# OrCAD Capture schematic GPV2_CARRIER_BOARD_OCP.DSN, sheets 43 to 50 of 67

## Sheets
43 049 I2C GPIO: size C
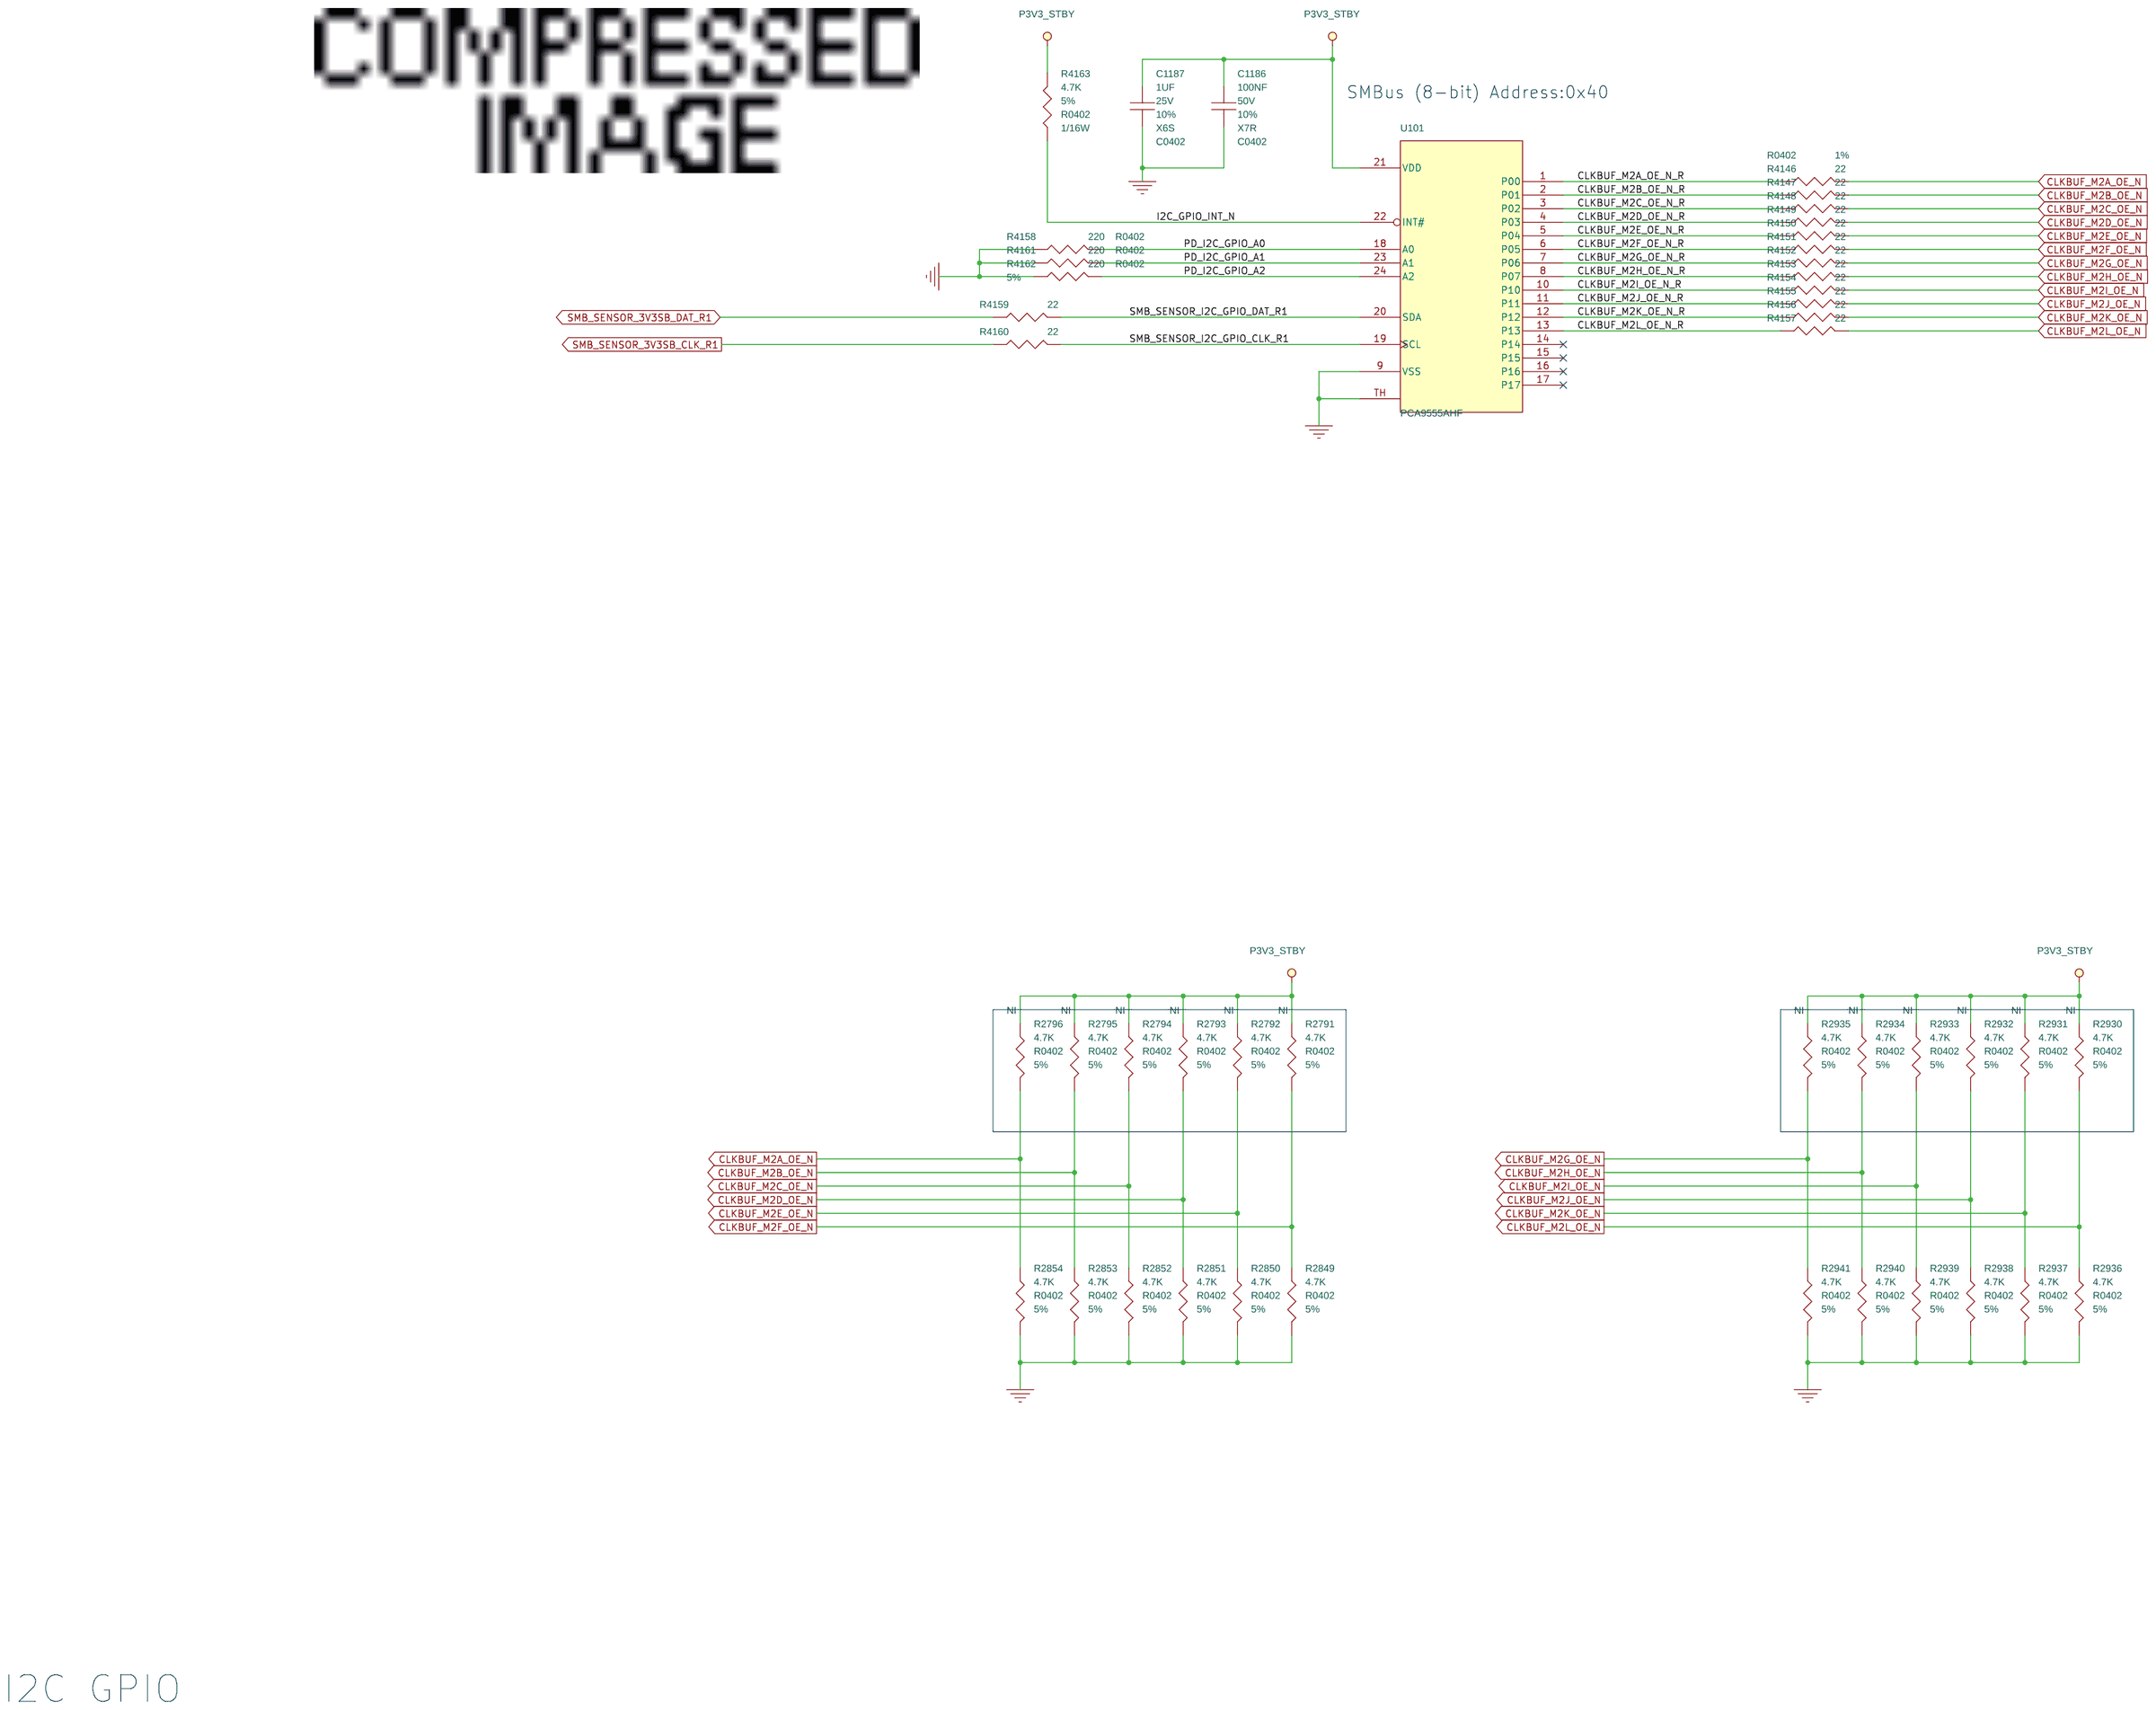
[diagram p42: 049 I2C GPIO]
44 050 Level Shifter 3: size C
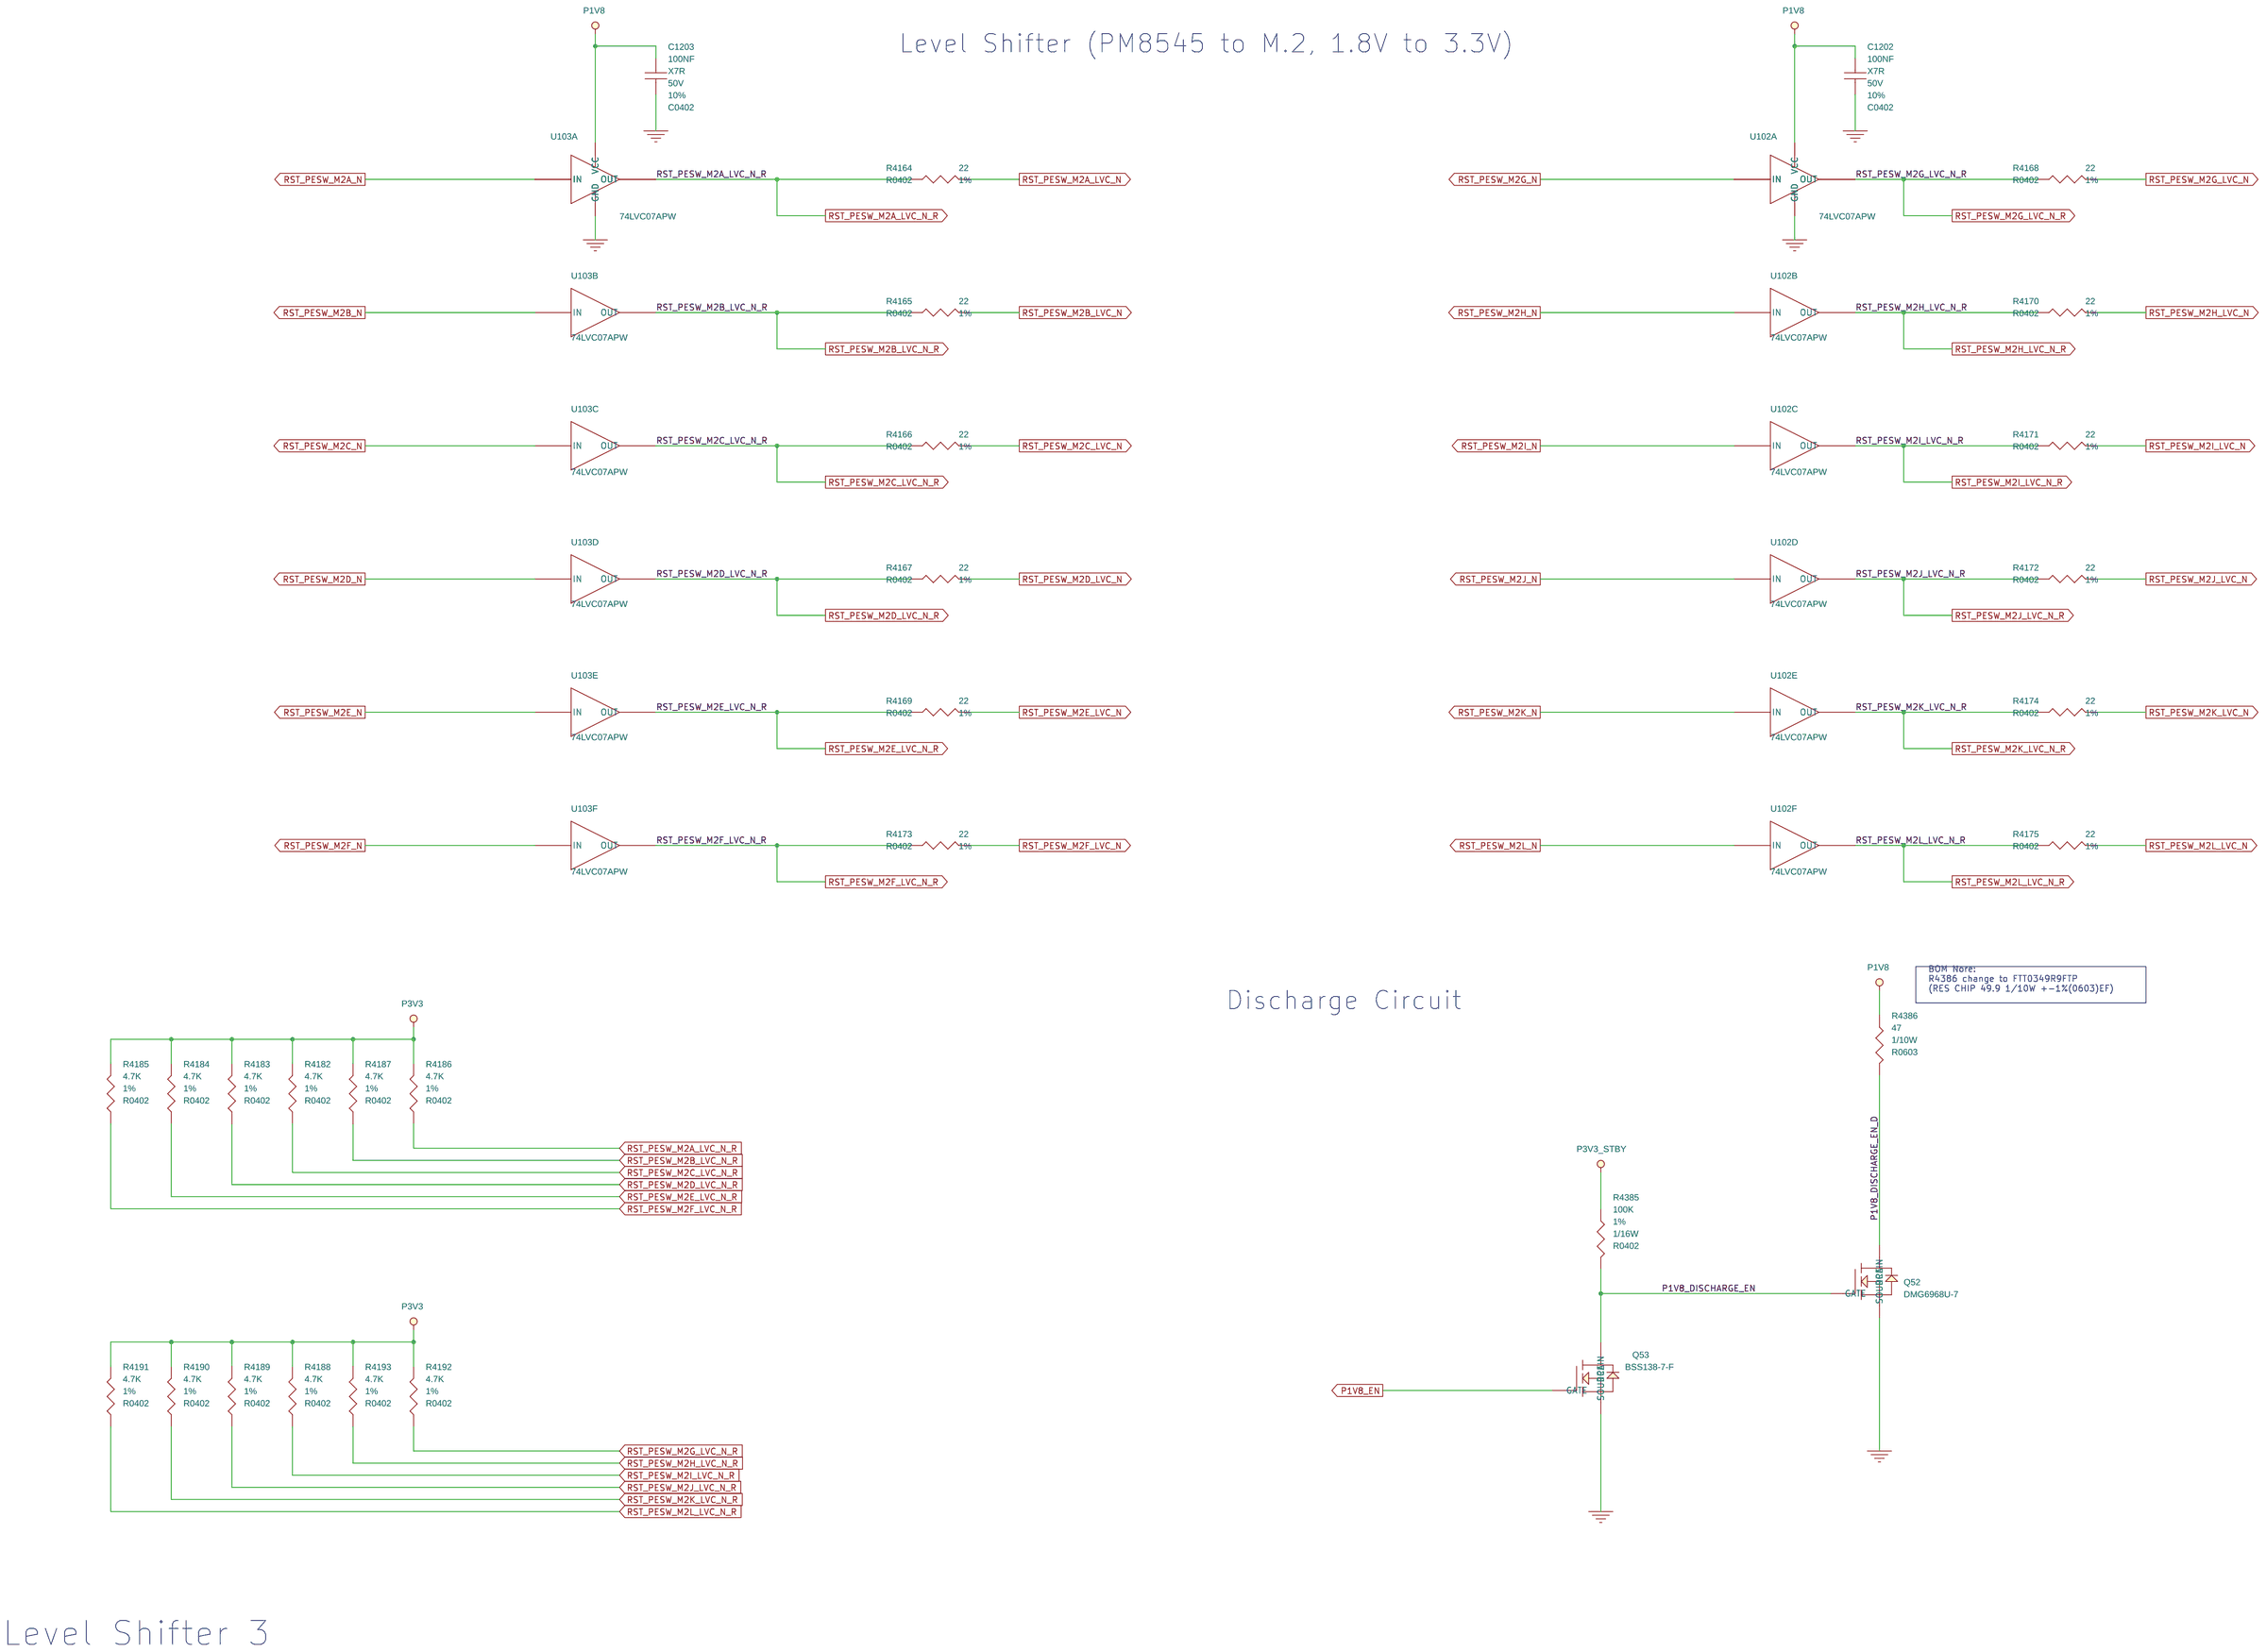
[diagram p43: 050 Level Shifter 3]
45 051 TEMP SENSOR & FRU: size C
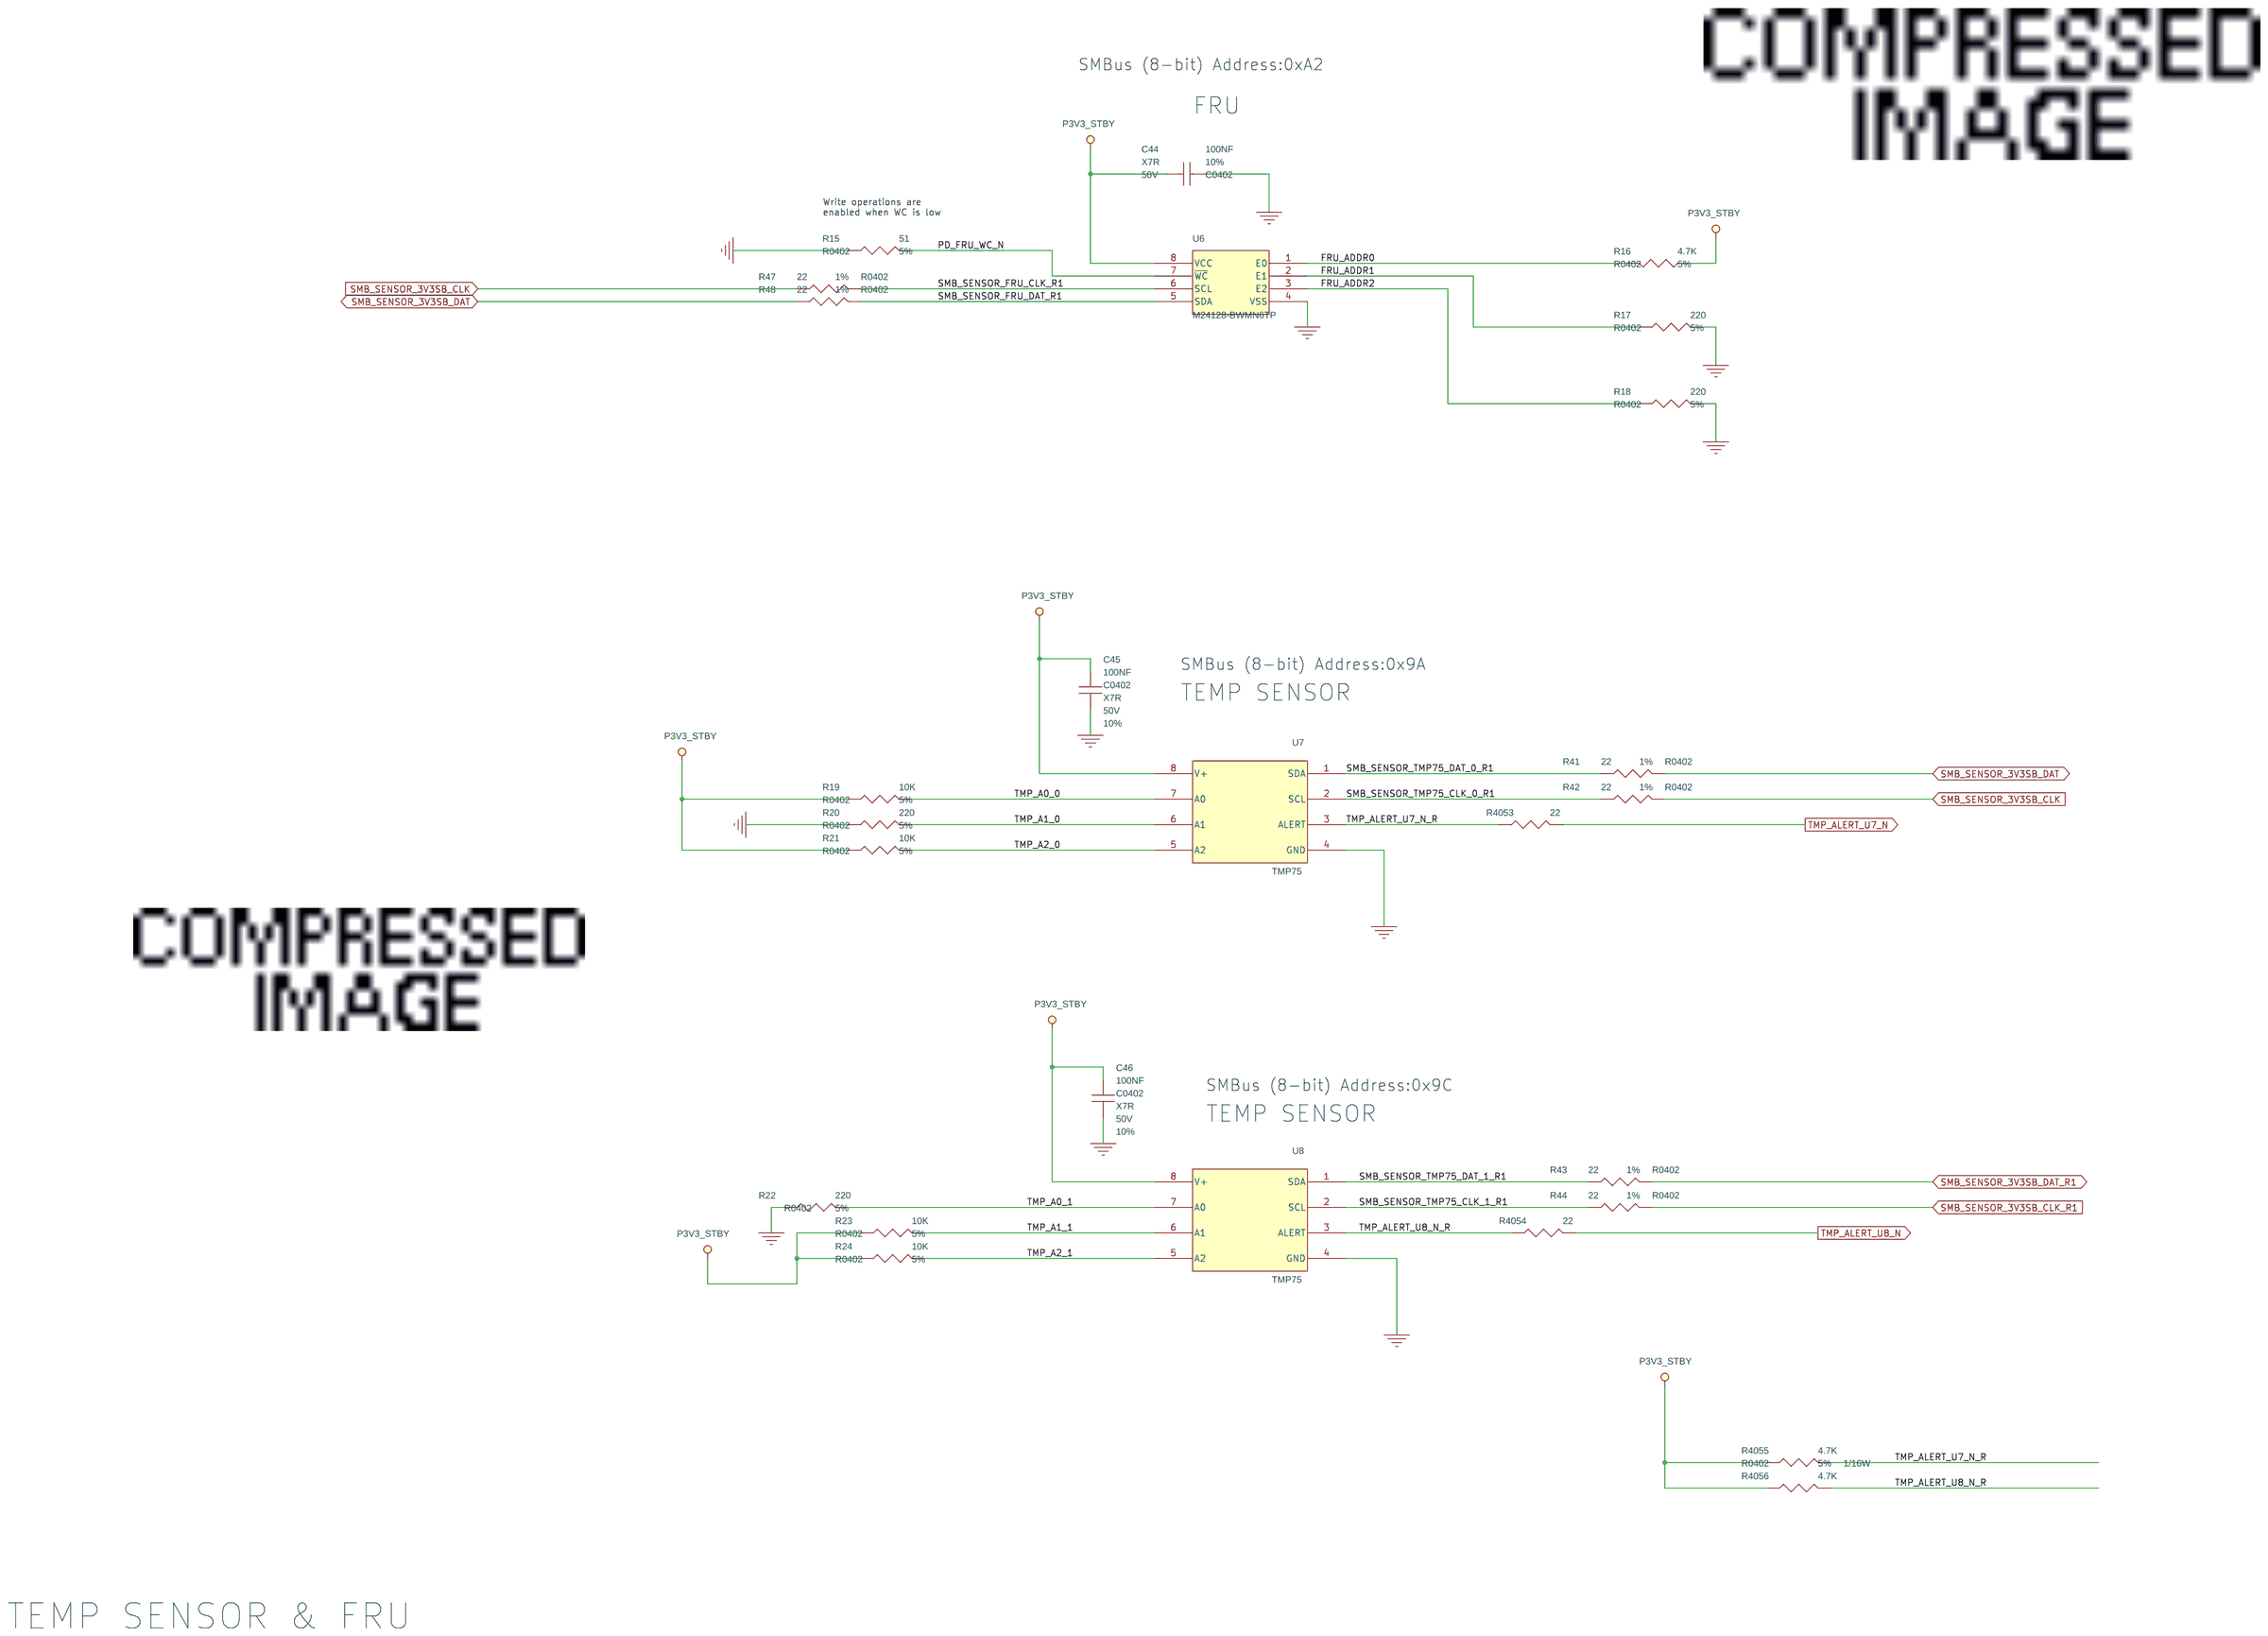
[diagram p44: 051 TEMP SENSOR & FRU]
46 052 BIC_SNOWLAKE 1: size C
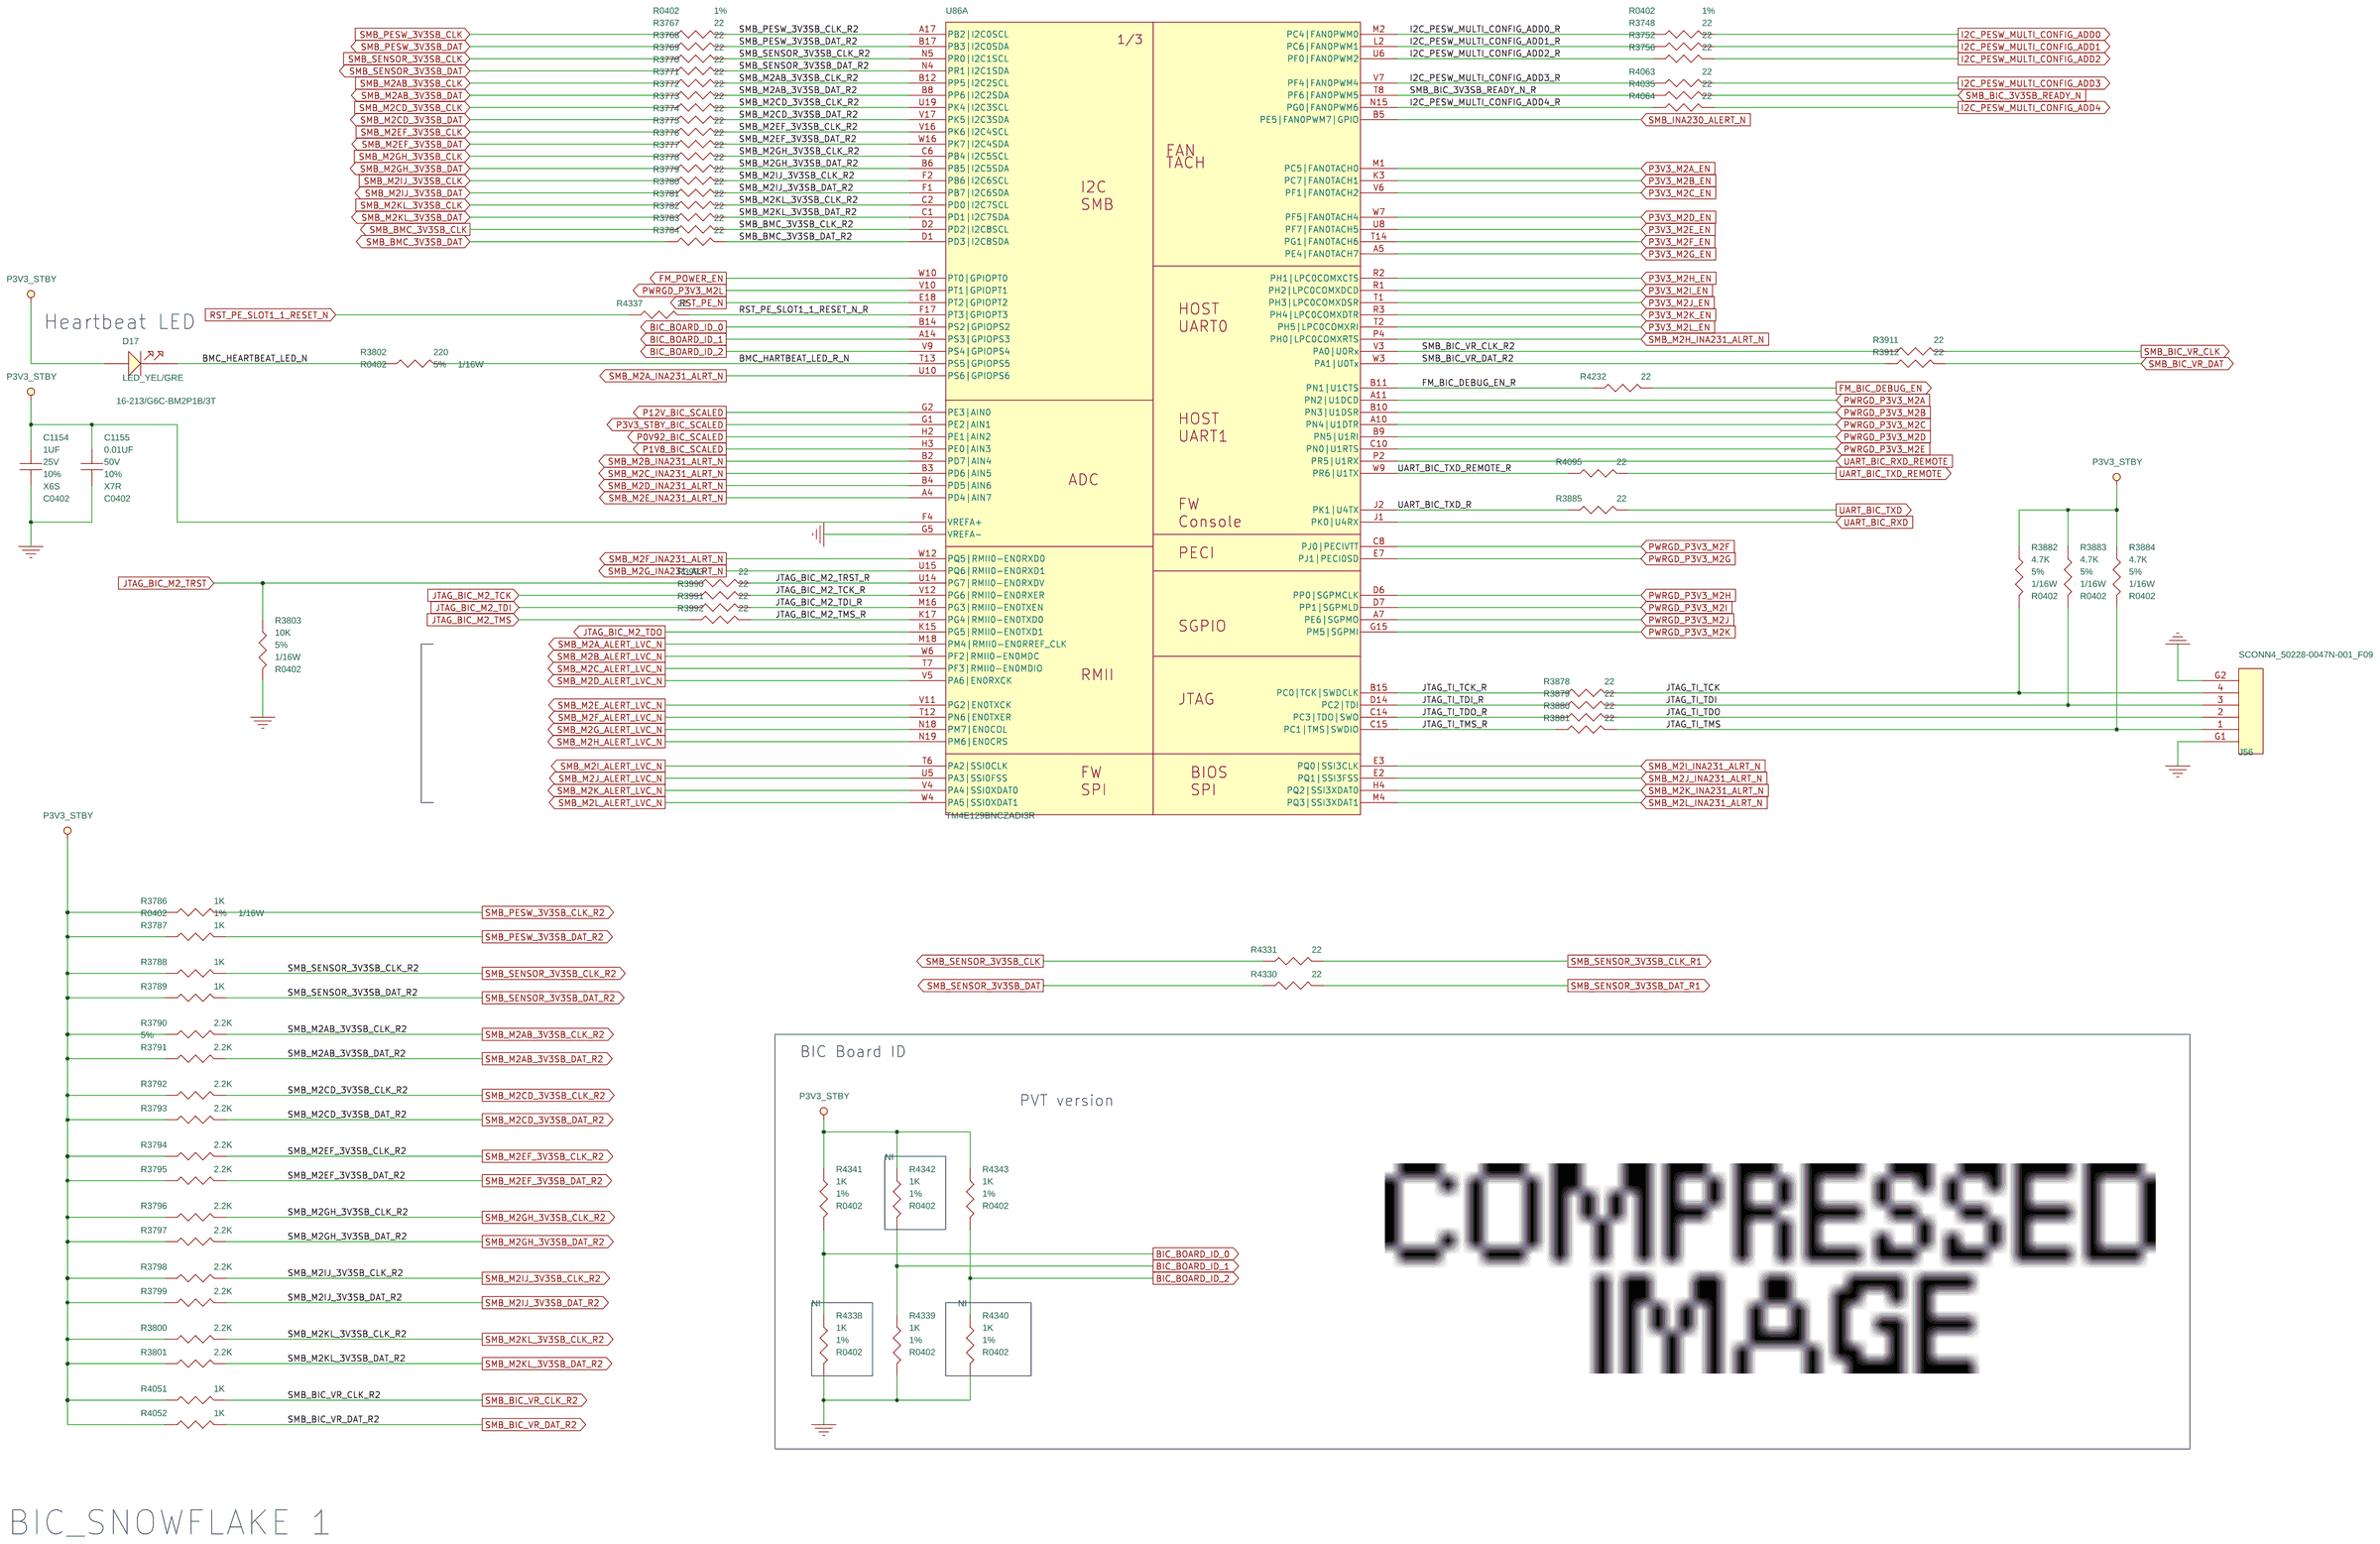
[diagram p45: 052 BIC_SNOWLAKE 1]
47 053 BIC_SNOWLAKE 2: size C
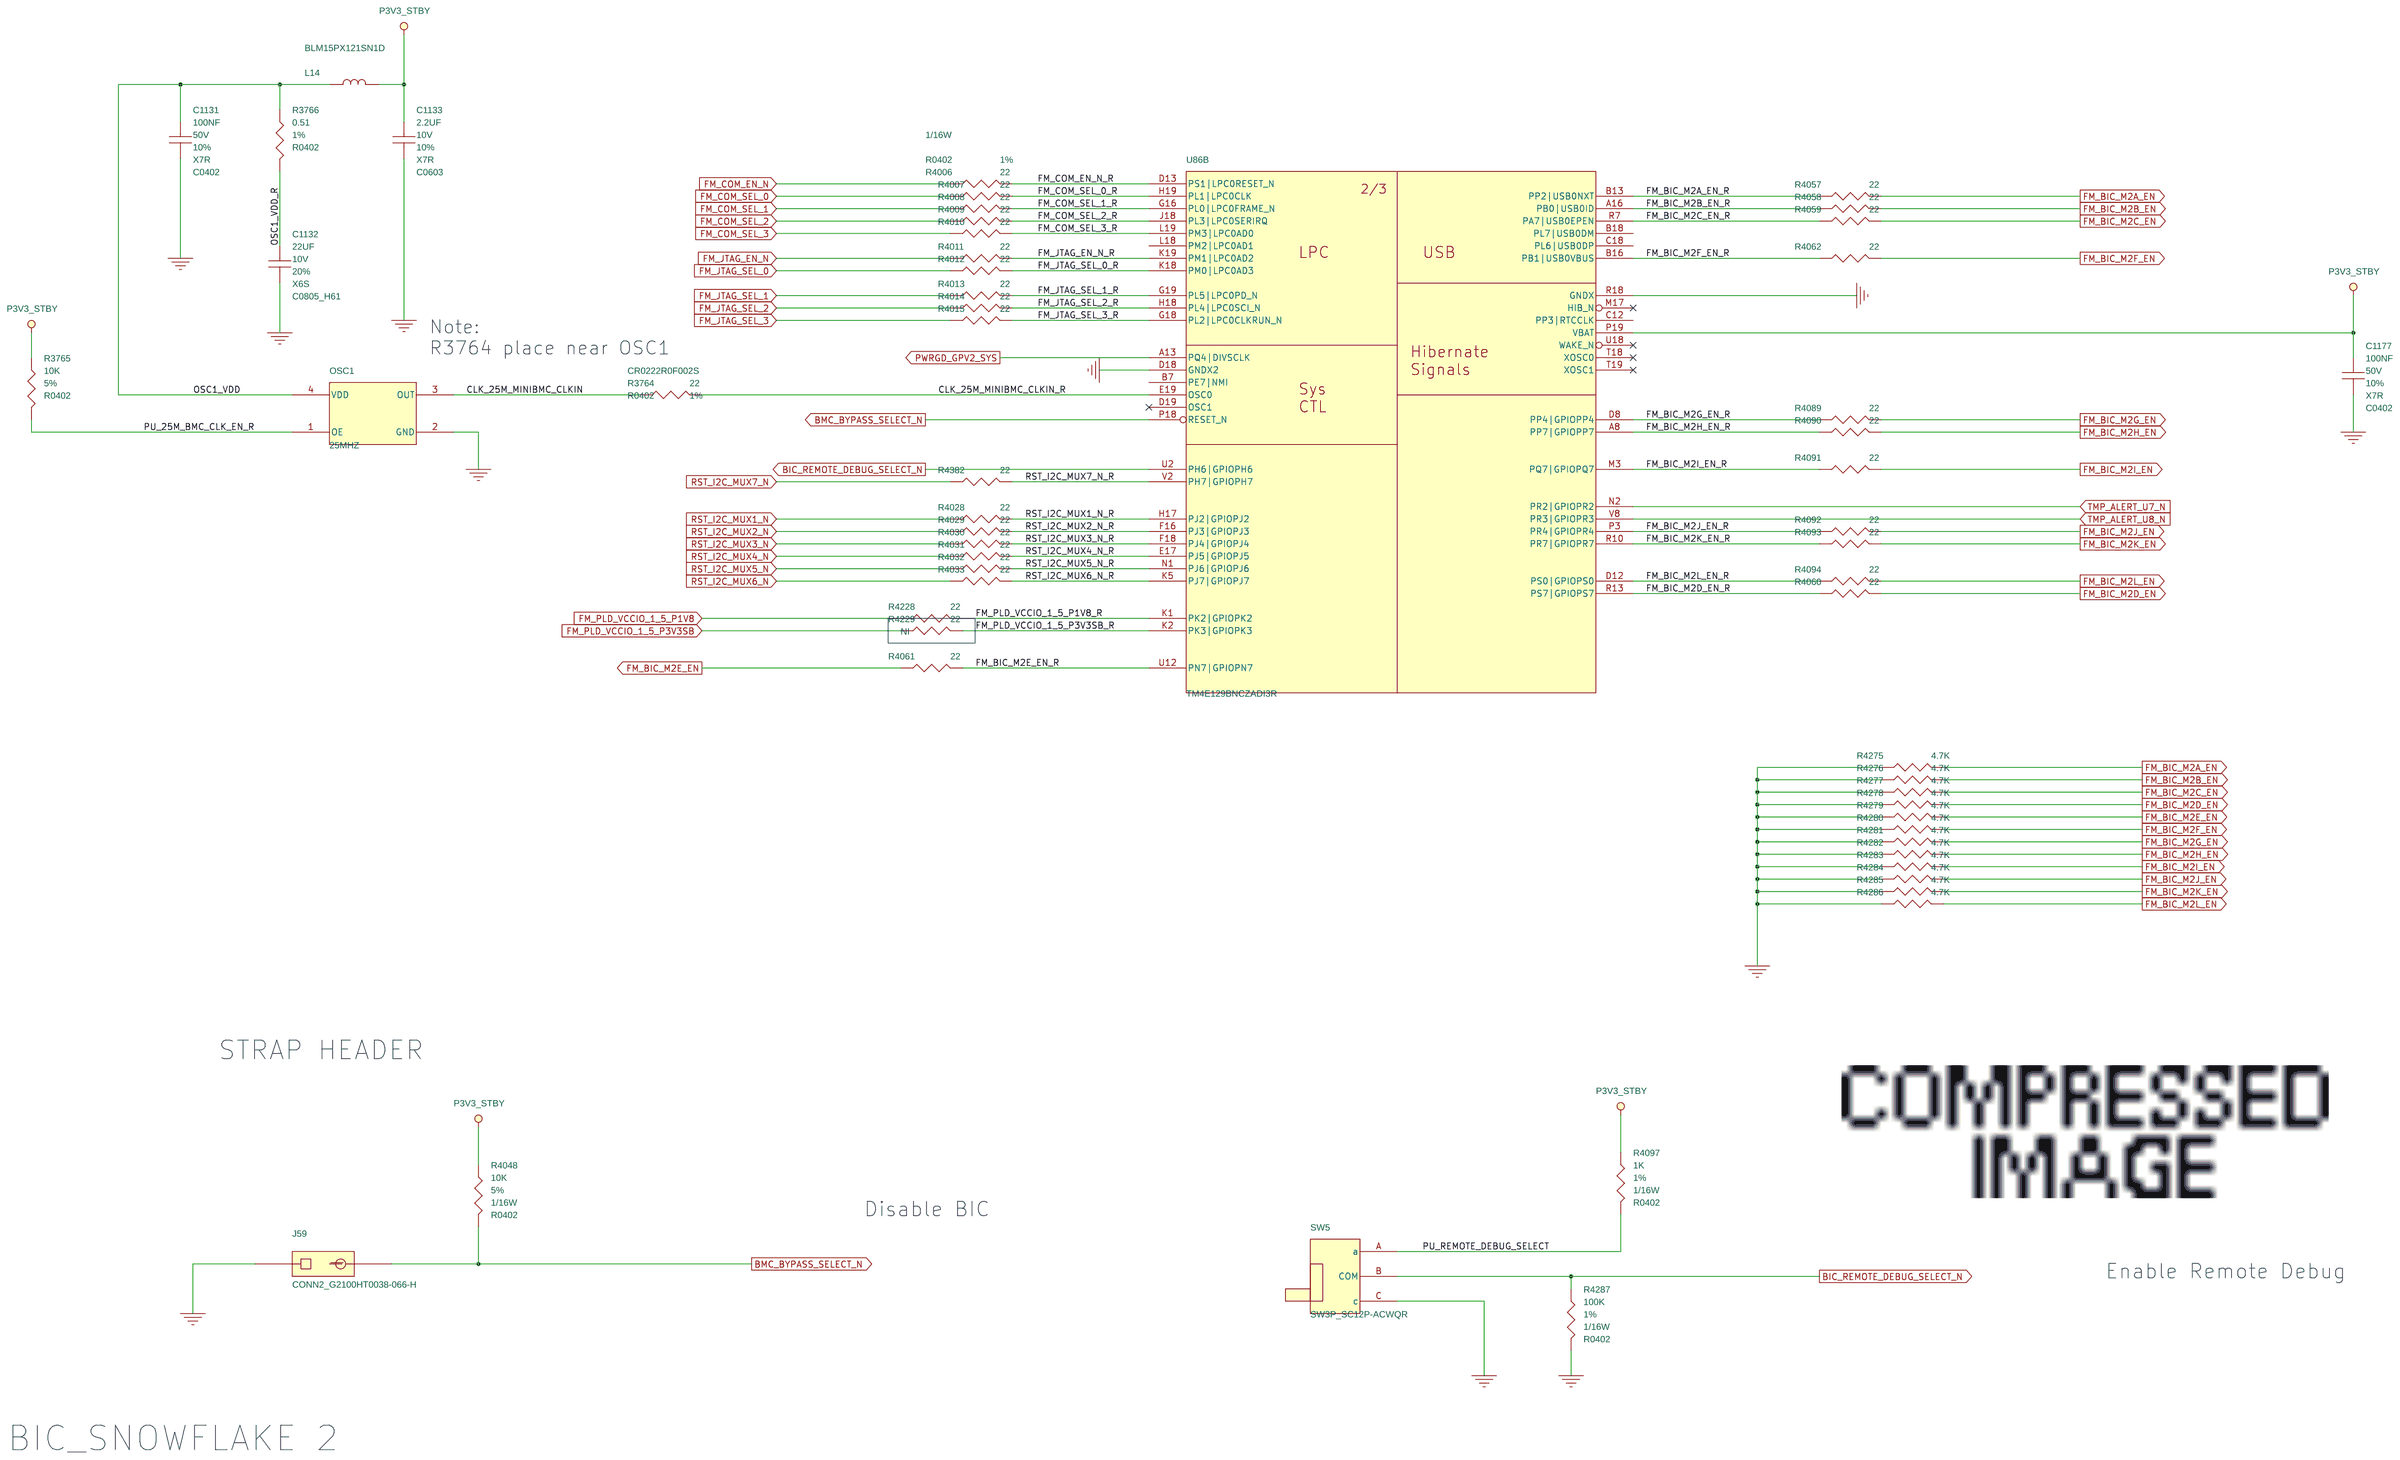
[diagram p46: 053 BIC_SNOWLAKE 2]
48 054 BIC_SNOWLAKE 3: size C
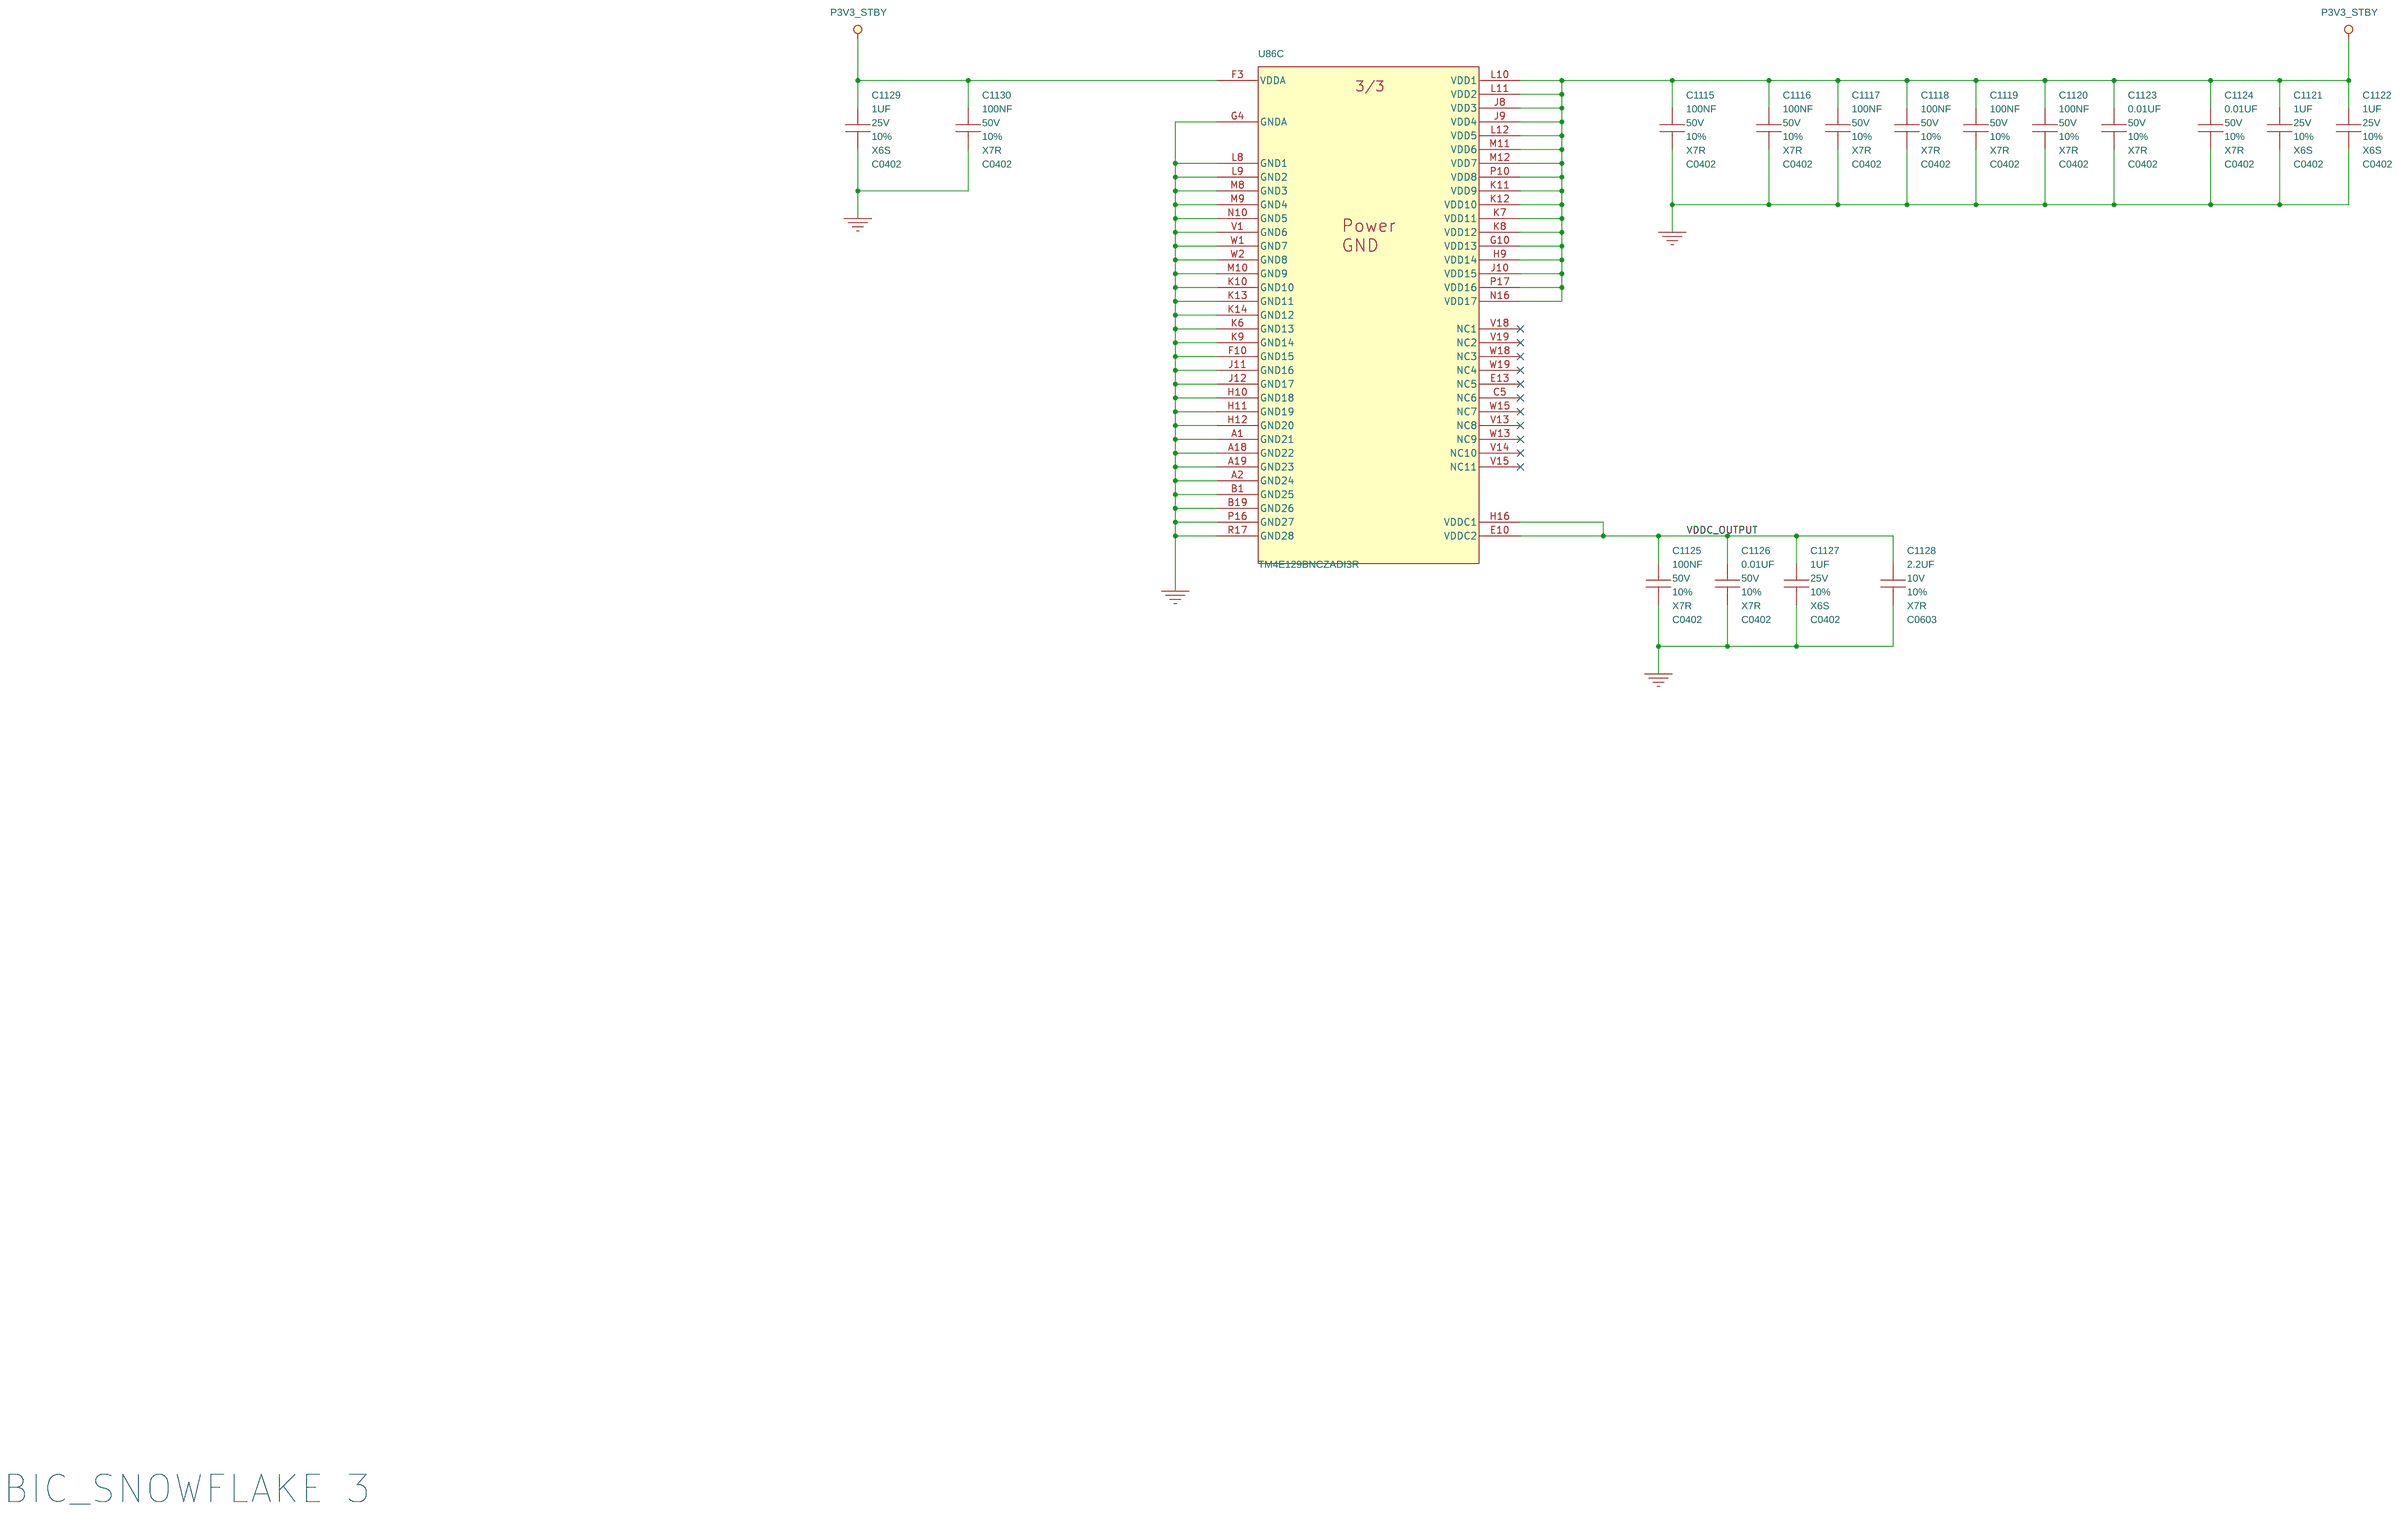
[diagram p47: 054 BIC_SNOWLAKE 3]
49 055 Level Shifter 4: size C
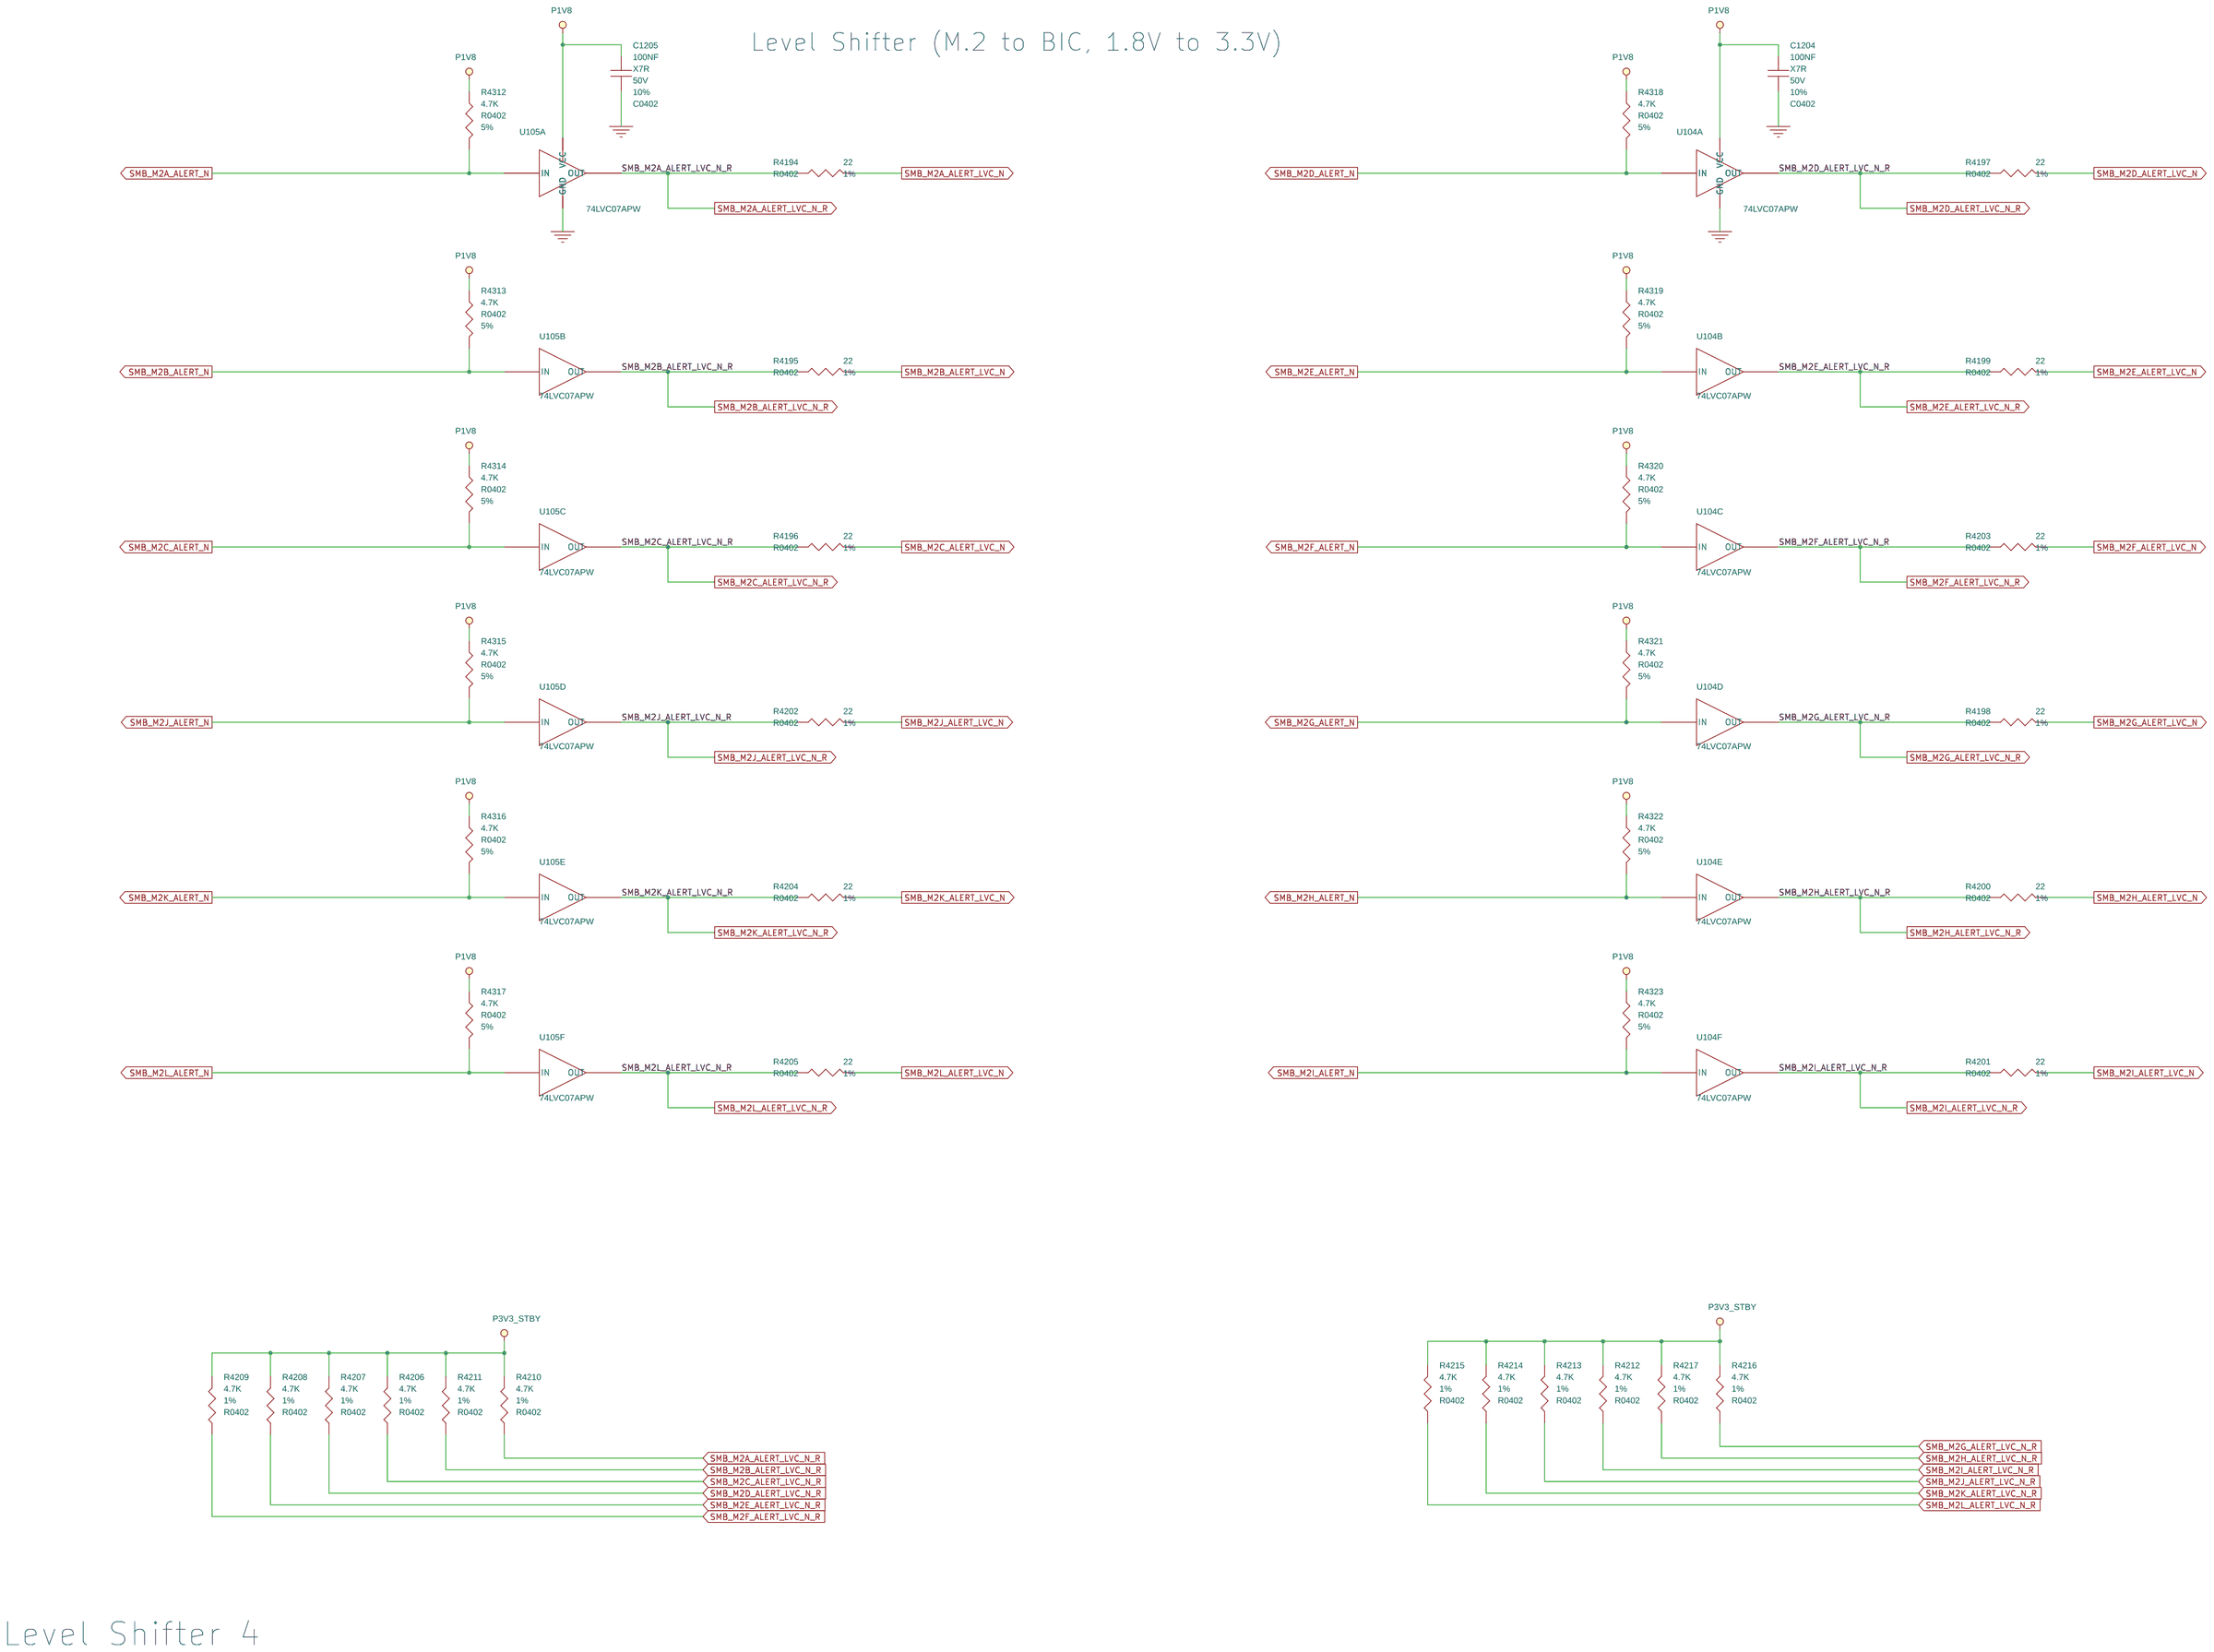
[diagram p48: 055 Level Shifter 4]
50 056 BIC-VOLTAGE MONITOR: size C
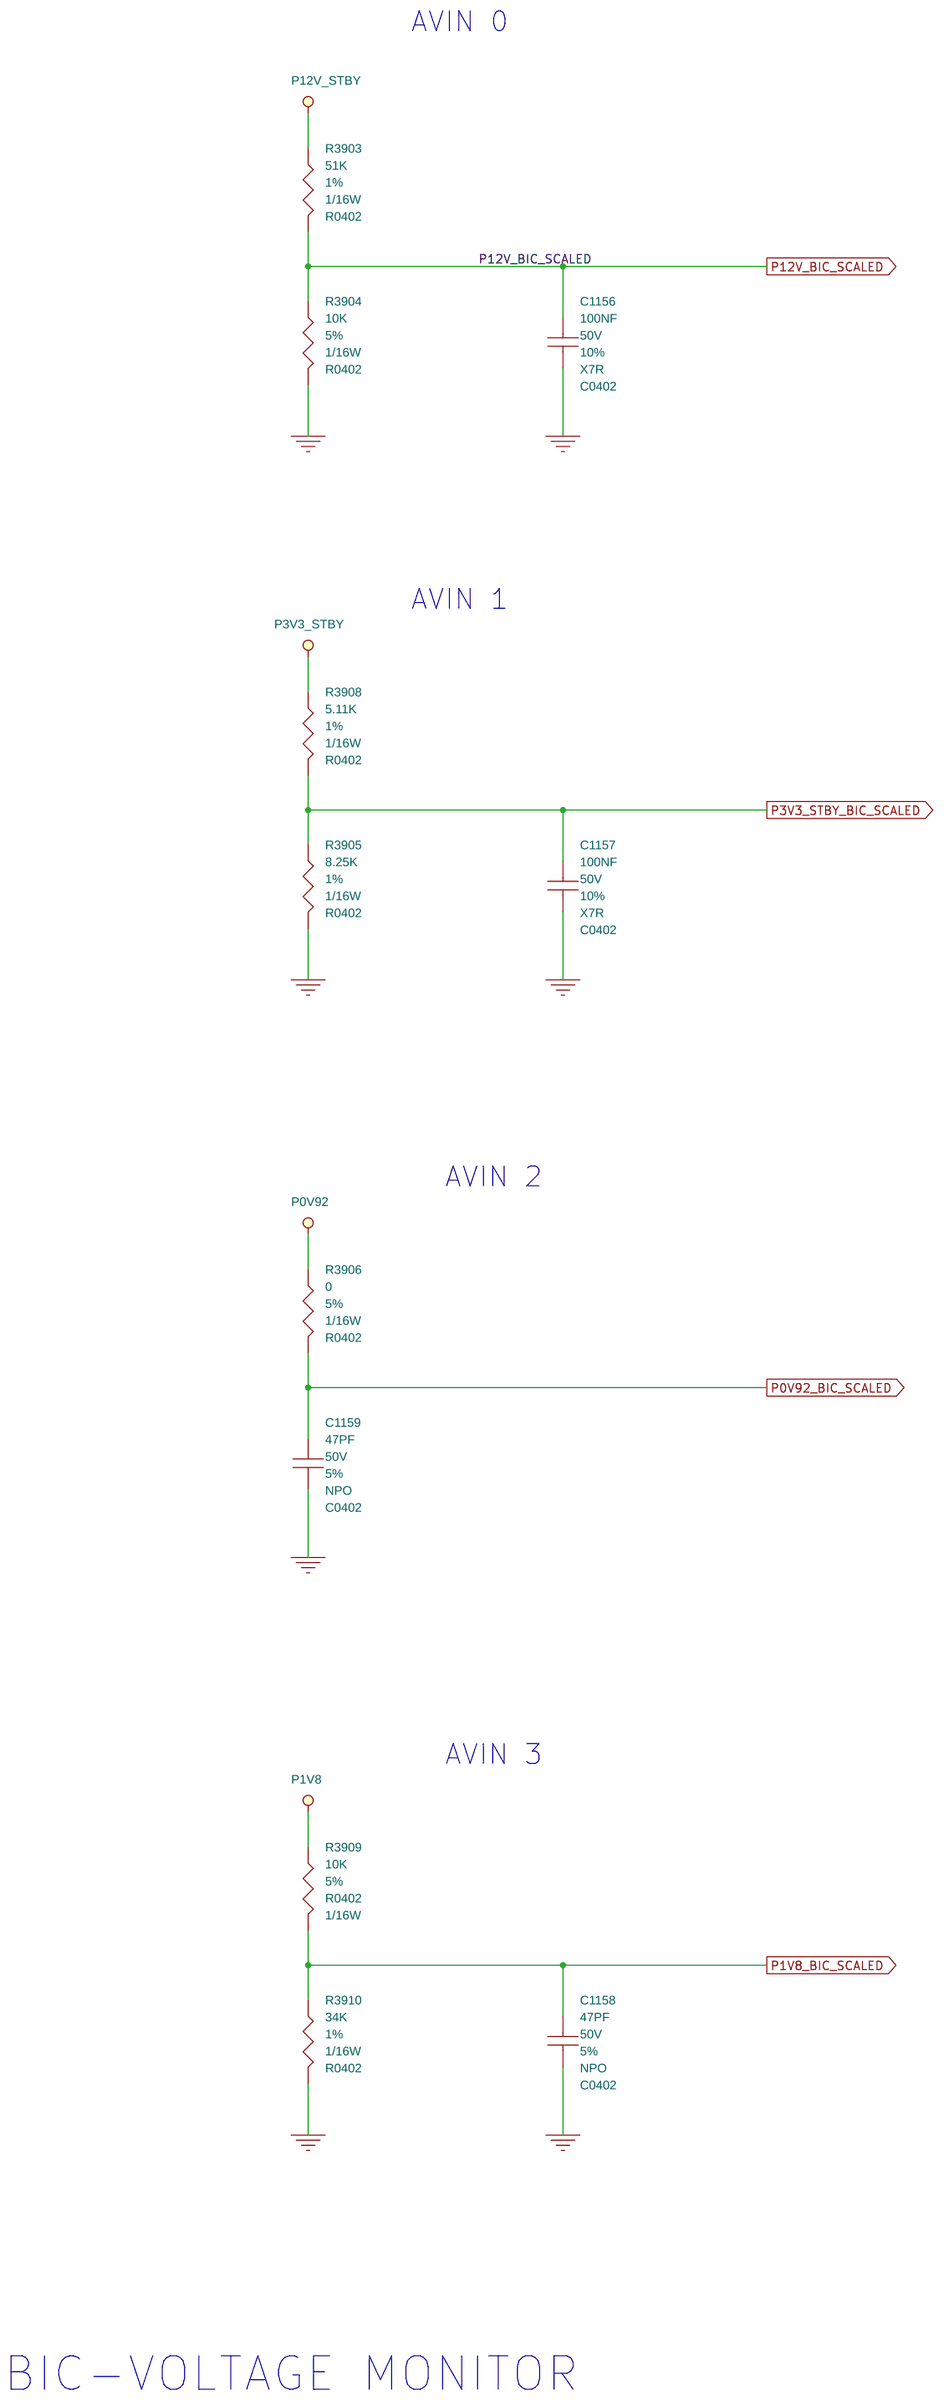
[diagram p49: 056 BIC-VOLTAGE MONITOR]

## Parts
sheet 049 I2C GPIO
C1186  100NF  [C0402]
C1187  1UF  [C0402]
R2791  4.7K  [R0402]
R2792  4.7K  [R0402]
R2793  4.7K  [R0402]
R2794  4.7K  [R0402]
R2795  4.7K  [R0402]
R2796  4.7K  [R0402]
R2849  4.7K  [R0402]
R2850  4.7K  [R0402]
R2851  4.7K  [R0402]
R2852  4.7K  [R0402]
R2853  4.7K  [R0402]
R2854  4.7K  [R0402]
R2930  4.7K  [R0402]
R2931  4.7K  [R0402]
R2932  4.7K  [R0402]
R2933  4.7K  [R0402]
R2934  4.7K  [R0402]
R2935  4.7K  [R0402]
R2936  4.7K  [R0402]
R2937  4.7K  [R0402]
R2938  4.7K  [R0402]
R2939  4.7K  [R0402]
R2940  4.7K  [R0402]
R2941  4.7K  [R0402]
R4146  22  [R0402]
R4147  22  [R0402]
R4148  22  [R0402]
R4149  22  [R0402]
R4150  22  [R0402]
R4151  22  [R0402]
R4152  22  [R0402]
R4153  22  [R0402]
R4154  22  [R0402]
R4155  22  [R0402]
R4156  22  [R0402]
R4157  22  [R0402]
R4158  220  [R0402]
R4159  22  [R0402]
R4160  22  [R0402]
R4161  220  [R0402]
R4162  220  [R0402]
R4163  4.7K  [R0402]
U101  PCA9555AHF  [HWQFN24_0-5_4X4]
sheet 050 Level Shifter 3
C1202  100NF  [C0402]
C1203  100NF  [C0402]
Q52  DMG6968U-7  [SOT23_GDSXC]
Q53  BSS138-7-F  [SOT23_GDSXC]
R4164  22  [R0402]
R4165  22  [R0402]
R4166  22  [R0402]
R4167  22  [R0402]
R4168  22  [R0402]
R4169  22  [R0402]
R4170  22  [R0402]
R4171  22  [R0402]
R4172  22  [R0402]
R4173  22  [R0402]
R4174  22  [R0402]
R4175  22  [R0402]
R4182  4.7K  [R0402]
R4183  4.7K  [R0402]
R4184  4.7K  [R0402]
R4185  4.7K  [R0402]
R4186  4.7K  [R0402]
R4187  4.7K  [R0402]
R4188  4.7K  [R0402]
R4189  4.7K  [R0402]
R4190  4.7K  [R0402]
R4191  4.7K  [R0402]
R4192  4.7K  [R0402]
R4193  4.7K  [R0402]
R4385  100K  [R0402]
R4386  47  [R0603]
U102  74LVC07APW  [TSSOP14]  (sections A,B,C,D,E,F)
U103  74LVC07APW  [TSSOP14]  (sections A,B,C,D,E,F)
sheet 051 TEMP SENSOR & FRU
C44  100NF  [C0402]
C45  100NF  [C0402]
C46  100NF  [C0402]
R15  51  [R0402]
R16  4.7K  [R0402]
R17  220  [R0402]
R18  220  [R0402]
R19  10K  [R0402]
R20  220  [R0402]
R21  10K  [R0402]
R22  220  [R0402]
R23  10K  [R0402]
R24  10K  [R0402]
R41  22  [R0402]
R42  22  [R0402]
R43  22  [R0402]
R44  22  [R0402]
R47  22  [R0402]
R48  22  [R0402]
R4053  22  [R0402]
R4054  22  [R0402]
R4055  4.7K  [R0402]
R4056  4.7K  [R0402]
U6  M24128-BWMN6TP  [SOIC8XH]
U7  TMP75  [MSOP8]
U8  TMP75  [MSOP8]
sheet 052 BIC_SNOWLAKE 1
C1154  1UF  [C0402]
C1155  0.01UF  [C0402]
D17  LED_YEL/GRE  [LED_16213XA]
J56  SCONN4_50228-0047N-001_F09  [CON_4S1H2S_P1XA_F09]
R3748  22  [R0402]
R3752  22  [R0402]
R3756  22  [R0402]
R3767  22  [R0402]
R3768  22  [R0402]
R3769  22  [R0402]
R3770  22  [R0402]
R3771  22  [R0402]
R3772  22  [R0402]
R3773  22  [R0402]
R3774  22  [R0402]
R3775  22  [R0402]
R3776  22  [R0402]
R3777  22  [R0402]
R3778  22  [R0402]
R3779  22  [R0402]
R3780  22  [R0402]
R3781  22  [R0402]
R3782  22  [R0402]
R3783  22  [R0402]
R3784  22  [R0402]
R3786  1K  [R0402]
R3787  1K  [R0402]
R3788  1K  [R0402]
R3789  1K  [R0402]
R3790  2.2K  [R0402]
R3791  2.2K  [R0402]
R3792  2.2K  [R0402]
R3793  2.2K  [R0402]
R3794  2.2K  [R0402]
R3795  2.2K  [R0402]
R3796  2.2K  [R0402]
R3797  2.2K  [R0402]
R3798  2.2K  [R0402]
R3799  2.2K  [R0402]
R3800  2.2K  [R0402]
R3801  2.2K  [R0402]
R3802  220  [R0402]
R3803  10K  [R0402]
R3878  22  [R0402]
R3879  22  [R0402]
R3880  22  [R0402]
R3881  22  [R0402]
R3882  4.7K  [R0402]
R3883  4.7K  [R0402]
R3884  4.7K  [R0402]
R3885  22  [R0402]
R3911  22  [R0402]
R3912  22  [R0402]
R3990  22  [R0402]
R3991  22  [R0402]
R3992  22  [R0402]
R3993  22  [R0402]
R4035  22  [R0402]
R4051  1K  [R0402]
R4052  1K  [R0402]
R4063  22  [R0402]
R4064  22  [R0402]
R4095  22  [R0402]
R4232  22  [R0402]
R4330  22  [R0402]
R4331  22  [R0402]
R4337  22  [R0402]
R4338  1K  [R0402]
R4339  1K  [R0402]
R4340  1K  [R0402]
R4341  1K  [R0402]
R4342  1K  [R0402]
R4343  1K  [R0402]
U86  TM4E129BNCZADI3R  [BGA212]  (sections A,B,C)
sheet 053 BIC_SNOWLAKE 2
C1131  100NF  [C0402]
C1132  22UF  [C0805_H61]
C1133  2.2UF  [C0603]
C1177  100NF  [C0402]
J59  CONN2_G2100HT0038-066-H  [HEADER1X2XJ_H339]
L14  BLM15PX121SN1D  [L0402]
OSC1  25MHZ  [OSC4_FJ2500009]
R3764  22  [R0402]
R3765  10K  [R0402]
R3766  0.51  [R0402]
R4006  22  [R0402]
R4007  22  [R0402]
R4008  22  [R0402]
R4009  22  [R0402]
R4010  22  [R0402]
R4011  22  [R0402]
R4012  22  [R0402]
R4013  22  [R0402]
R4014  22  [R0402]
R4015  22  [R0402]
R4028  22  [R0402]
R4029  22  [R0402]
R4030  22  [R0402]
R4031  22  [R0402]
R4032  22  [R0402]
R4033  22  [R0402]
R4048  10K  [R0402]
R4057  22  [R0402]
R4058  22  [R0402]
R4059  22  [R0402]
R4060  22  [R0402]
R4061  22  [R0402]
R4062  22  [R0402]
R4089  22  [R0402]
R4090  22  [R0402]
R4091  22  [R0402]
R4092  22  [R0402]
R4093  22  [R0402]
R4094  22  [R0402]
R4097  1K  [R0402]
R4228  22  [R0402]
R4229  22  [R0402]
R4275  4.7K  [R0402]
R4276  4.7K  [R0402]
R4277  4.7K  [R0402]
R4278  4.7K  [R0402]
R4279  4.7K  [R0402]
R4280  4.7K  [R0402]
R4281  4.7K  [R0402]
R4282  4.7K  [R0402]
R4283  4.7K  [R0402]
R4284  4.7K  [R0402]
R4285  4.7K  [R0402]
R4286  4.7K  [R0402]
R4287  100K  [R0402]
R4382  22  [R0402]
SW5  SW3P_SC12P-ACWQR  [SW_RD15P4P]
sheet 054 BIC_SNOWLAKE 3
C1115  100NF  [C0402]
C1116  100NF  [C0402]
C1117  100NF  [C0402]
C1118  100NF  [C0402]
C1119  100NF  [C0402]
C1120  100NF  [C0402]
C1121  1UF  [C0402]
C1122  1UF  [C0402]
C1123  0.01UF  [C0402]
C1124  0.01UF  [C0402]
C1125  100NF  [C0402]
C1126  0.01UF  [C0402]
C1127  1UF  [C0402]
C1128  2.2UF  [C0603]
C1129  1UF  [C0402]
C1130  100NF  [C0402]
sheet 055 Level Shifter 4
C1204  100NF  [C0402]
C1205  100NF  [C0402]
R4194  22  [R0402]
R4195  22  [R0402]
R4196  22  [R0402]
R4197  22  [R0402]
R4198  22  [R0402]
R4199  22  [R0402]
R4200  22  [R0402]
R4201  22  [R0402]
R4202  22  [R0402]
R4203  22  [R0402]
R4204  22  [R0402]
R4205  22  [R0402]
R4206  4.7K  [R0402]
R4207  4.7K  [R0402]
R4208  4.7K  [R0402]
R4209  4.7K  [R0402]
R4210  4.7K  [R0402]
R4211  4.7K  [R0402]
R4212  4.7K  [R0402]
R4213  4.7K  [R0402]
R4214  4.7K  [R0402]
R4215  4.7K  [R0402]
R4216  4.7K  [R0402]
R4217  4.7K  [R0402]
R4312  4.7K  [R0402]
R4313  4.7K  [R0402]
R4314  4.7K  [R0402]
R4315  4.7K  [R0402]
R4316  4.7K  [R0402]
R4317  4.7K  [R0402]
R4318  4.7K  [R0402]
R4319  4.7K  [R0402]
R4320  4.7K  [R0402]
R4321  4.7K  [R0402]
R4322  4.7K  [R0402]
R4323  4.7K  [R0402]
U104  74LVC07APW  [TSSOP14]  (sections A,B,C,D,E,F)
U105  74LVC07APW  [TSSOP14]  (sections A,B,C,D,E,F)
sheet 056 BIC-VOLTAGE MONITOR
C1156  100NF  [C0402]
C1157  100NF  [C0402]
C1158  47PF  [C0402]
C1159  47PF  [C0402]
R3903  51K  [R0402]
R3904  10K  [R0402]
R3905  8.25K  [R0402]
R3906  0  [R0402]
R3908  5.11K  [R0402]
R3909  10K  [R0402]
R3910  34K  [R0402]

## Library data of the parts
C44 C1115-C1120 C1125 C1130 C1131 C1156 C1157 C1177 C1186 = CAP_NP: CAP CHIP 100NF 50V(+-10%,X7R,0402); CLASS: DISCRETE; MATERIAL: X7R; Manuf_PN: CC0402KRX7R9BB104; Manuf_name: YAGEO CORPORATION; Manuftr: YGO; Part_Type: *LF_C0402; TOLERANCE: 10%; VOLTAGE: 50V
C1121 C1122 C1127 C1129 C1154 C1187 = CAP_NP: CAP CHIP 1UF 25V(+-10%,X6S,0402); CLASS: DISCRETE; MATERIAL: X6S; Manuf_PN: GRM155C81E105K; Manuf_name: MURATA ERIE N.A. INC TAIWAN BRANCH Okayama Murata Mfg.Co..Ltd.Wakura Murata Mfg.; Manuftr: MUR; Part_Type: *LF_C0402; TOLERANCE: 10%; VOLTAGE: 25V
R2791-R2796 R2930-R2935 = R: RES CHIP 4.7K 1/16W +-5% (0402); CLASS: DISCRETE; MATERIAL: CHIP; Manuf_PN: RR0510S-472-JN; Manuf_name: CYNTEC CO.. LTD.; Manufacturer: CYN; Manuftr: CYN; Not_insert: NI; Part_Type: *LF_Resistor; TOLERANCE: 5%; WATTAGE: 1/16W
R16 R2849-R2854 R2936-R2941 R4312-R4323 = R: RES CHIP 4.7K 1/16W +-5% (0402); CLASS: DISCRETE; MATERIAL: CHIP; Manuf_PN: RR0510S-472-JN; Manuf_name: CYNTEC CO.. LTD.; Manufacturer: CYN; Manuftr: CYN; Part_Type: *LF_Resistor; TOLERANCE: 5%; WATTAGE: 1/16W
R3748 R3752 R3756 R3764 R3767-R3784 R3878-R3881 R3885 R3911 R3912 R3990-R3993 R4007-R4015 R4028-R4033 R4035 R4053 R4054 R4057-R4064 R4089-R4095 R4146-R4157 R4159 R4160 R4164-R4175 R4194-R4205 R4228 R4232 R4330 R4331 R4337 R4382 = R: RES CHIP 22 1/16W +-1%(0402); CLASS: DISCRETE; MATERIAL: CHIP; Manuf_PN: CR0222R0F002S; Manuf_name: RTECH TECHNOLOGY CO..LTD. (Compostar); Manuftr: RHT; Part_Type: *LF_Resistor; TOLERANCE: 1%; WATTAGE: 1/16W
R20 R22 R3802 R4158 R4161 R4162 = R: RES CHIP 220 1/16W +-5%(0402); CLASS: DISCRETE; MATERIAL: CHIP; Manuf_PN: RR0510S-221-JN; Manuf_name: CYNTEC CO.. LTD.; Manuftr: CYN; Part_Type: *LF_Resistor; TOLERANCE: 5%; WATTAGE: 1/16W
R3882-R3884 R4055 R4056 R4163 R4275-R4286 = R: RES CHIP 4.7K 1/16W +-5% (0402); CLASS: DISCRETE; MATERIAL: CHIP; Manuf_PN: RR0510S-472-JN; Manuf_name: CYNTEC CO.. LTD.; Manuftr: CYN; Part_Type: *LF_Resistor; TOLERANCE: 5%; WATTAGE: 1/16W
U101 = PCA9555AHF: IC OTHER(24P)PCA9555AHF(HWQFN); CLASS: IC; MATERIAL: IC; Manuf_name: NXP semiconductors; Manuftr: NXP; Part_Type: *LF_Chipset
C45 C46 C1202-C1205 = CAP_NP: CAP CHIP 100NF 50V(+-10%,X7R,0402); CLASS: DISCRETE; MATERIAL: X7R; Manuf_PN: CC0402KRX7R9BB104; Manuf_name: YAGEO CORPORATION; Manufacturer: MUR; Manuftr: YGO; Part_Type: *LF_C0402; TOLERANCE: 10%; VOLTAGE: 50V
Q52 = MOSFET_N_GSD: TRANS MOS DMG6968U-7(20V,6.5A,1.3W)SOT23; CLASS: IC; MATERIAL: IC; Manuf_name: DIODES TAIWAN CO.,LTD.(Kai Hong Shanghai); Manuftr: DDS; Part_Type: *LF_Semiconductor
Q53 = MOSFET_N_0: TRANS MOSFET BSS138-7-F(50V,0.2A); CLASS: IC; MATERIAL: IC; Manuf_name: DIODES TAIWAN CO.,LTD.; Manuftr: DDS; Part_Type: *LF_Semiconductor
R4182-R4193 R4206-R4217 = R: RES CHIP 4.7K 1/16W +-1%(0402); CLASS: DISCRETE; MATERIAL: CHIP; Manuf_PN: RTT024701FTH; Manuf_name: RALEC ELECTRONIC CO.; Manuftr: RLC; Part_Type: *LF_Resistor; TOLERANCE: 1%; WATTAGE: 1/16W
R4385 = R: RES CHIP 100K 1/16W +-1%(0402)EF; CLASS: DISCRETE; FPLIST: R0402,R0402-0201; MATERIAL: CHIP; Manuf_PN: WR04X1003FTR; Manuf_name: WALSIN TECHNOLOGY CORPORATION; Manuftr: WTC; Part_Type: *LF_Resistor; TOLERANCE: 1%; WATTAGE: 1/16W
R4386 = R: RES CHIP 47 1/10W +-1% (0603); CLASS: DISCRETE; MATERIAL: CHIP; Manuf_PN: CR0347R0F001S; Manuf_name: "RTECH TECHNOLOGY CO..LTD.(Compostar)"; Manuftr: RHT; Part_Type: *LF_Resistor; TOLERANCE: 1%; WATTAGE: 1/10W
U102-U105 = 74LVC07: IC(14P) 74LVC07APW(TSSOP); CLASS: IC; MATERIAL: IC; Manuf_name: PHILIPS TAIWAN LTD..; Manuftr: PHI; Part_Type: *LF_Chipset
R15 = R: RES CHIP 51 1/16W +-5%(0402); CLASS: DISCRETE; MATERIAL: CHIP; Manuf_PN: RR0510S-510-JN; Manuf_name: CYNTEC CO.. LTD.; Manufacturer: CYN; Manuftr: CYN; Part_Type: *LF_Resistor; SUBSYS: HW_RES; TOLERANCE: 5%; WATTAGE: 1/16W
R17 R18 = R: RES CHIP 220 1/16W +-5%(0402); CLASS: DISCRETE; MATERIAL: CHIP; Manuf_PN: RR0510S-221-JN; Manuf_name: CYNTEC CO.. LTD.; Manufacturer: CYN; Manuftr: CYN; Part_Type: *LF_Resistor; SUBSYS: HW_RES; TOLERANCE: 5%; WATTAGE: 1/16W
R19 R21 R23 R24 R3765 R3803 R3904 R3909 R4048 = R: RES CHIP 10K 1/16W 5%(0402); CLASS: DISCRETE; MATERIAL: CHIP; Manuf_PN: RR0510S-103-JN; Manuf_name: CYNTEC CO.. LTD.; Manuftr: CYN; Part_Type: *LF_Resistor; TOLERANCE: 5%; WATTAGE: 1/16W
R41-R44 R47 R48 R4006 = R: RES CHIP 22 1/16W +-1%(0402); BOM: AST2300; CLASS: DISCRETE; MATERIAL: CHIP; Manuf_PN: CR0222R0F002S; Manuf_name: RTECH TECHNOLOGY CO..LTD. (Compostar); Manufacturer: CYN; Manuftr: RHT; Part_Type: *LF_Resistor; TOLERANCE: 1%; WATTAGE: 1/16W
U6 = M24128: IC(8P) EEPROM M24128-BWMN6TP(SO8); CLASS: IC; MATERIAL: IC; Manuf_name: SGS-THOMSON(STMicroelectronics); Manuftr: SGT; Part_Type: *LF_Chipset
U7 U8 = TMP75AIDGKR: IC(8P) TMP75AIDGKR (MSOP); CLASS: IC; MATERIAL: IC; Manuf_name: TEXAS INSTRUMENTS SUPPLY CO..; Manuftr: TIC; Part_Type: *LF_Chipset
C1123 C1124 C1126 C1155 = CAP_NP: CAP CHIP 0.01U 50V(+-10%,X7R,0402); CLASS: DISCRETE; MATERIAL: X7R; Manuf_PN: WBM155R71H103K; Manuf_name: MURATA ERIE N.A. INC TAIWAN BRANCH Okayama Murata Mfg.Co.,Ltd.; Manuftr: MUR; Part_Type: *LF_C0402; TOLERANCE: 10%; VOLTAGE: 50V
D17 = LED_0: LED SMD(2P)YEL/GRE(16-213/G6C-BM2P1B/3T); CLASS: IC; ESD_CDM: N/A; ESD_HBM: 2000; ESD_MM: N/A; MATERIAL: IC; MSD: NA; Manuf_PN: 16-213/G6C-BM2P1B/3T; Manuf_name: EVERLIGHT (EVERLIGHT ELECTRONICS CO., LTD. ); Manuftr: EVL; PIN_LENGTH_LONG_PIN: 0 MILS; PIN_LENGTH_SHORT_PIN: 0 MILS; Part_Type: *LF_Semiconductor
J56 = SCONN4_502280047N001: CONN SMD WAFER,4P,1R,MS(P1.0,H4.3)_FOR F09; CLASS: IO; MATERIAL: IO; Manuf_PN: 50228-0047N-001; Manuf_name: ACES ELECTRONIC CO., LTD.; Manuftr: ACS; Part_Type: *LF_Connector
R3786-R3789 R4051 R4052 R4097 = R: RES CHIP 1K 1/16W +-1% (0402); CLASS: DISCRETE; MATERIAL: CHIP; Manuf_PN: RR0510S-102-FN; Manuf_name: CYNTEC CO.. LTD.; Manuftr: CYN; Part_Type: *LF_Resistor; TOLERANCE: 1%; WATTAGE: 1/16W
R3790-R3801 = R: RES CHIP 2.2K 1/16W +-5%(0402)EF; CLASS: DISCRETE; FPLIST: R0402,R0402-0201; MATERIAL: CHIP; Manuf_PN: RC0402JR-072K2P; Manuf_name: YAGEO CORPORATION; Manuftr: YGO; Part_Type: *LF_Resistor; TOLERANCE: 5%; WATTAGE: 1/16W
R4338 R4340 R4342 = R: RES CHIP 1K 1/16W +-1% (0402); BOM: AST2300; CLASS: DISCRETE; FPLIST: R0402,R0402-0201; MATERIAL: CHIP; Manuf_PN: RR0510S-102-FN; Manuf_name: CYNTEC CO.. LTD.; Manufacturer: CYN; Manuftr: CYN; Not_insert: NI; Part_Type: *LF_Resistor; TOLERANCE: 1%; WATTAGE: 1/16W
R4339 R4341 R4343 = R: RES CHIP 1K 1/16W +-1% (0402); BOM: AST2300; CLASS: DISCRETE; FPLIST: R0402,R0402-0201; MATERIAL: CHIP; Manuf_PN: RR0510S-102-FN; Manuf_name: CYNTEC CO.. LTD.; Manufacturer: CYN; Manuftr: CYN; Part_Type: *LF_Resistor; TOLERANCE: 1%; WATTAGE: 1/16W
U86 = LM4FB15P9ZADHIN: IC CTRL(212P)TM4E129BNCZADI3R(BGA); CLASS: IC; MATERIAL: IC; Manuf_name: TEXAS INSTRUMENTS SUPPLY CO.,; Manuftr: TIC; Part_Type: *LF_Chipset
C1132 = CAP_NP: CAP CHIP 22U 10V(+-20%,X6S,0805)MUR; CLASS: DISCRETE; MATERIAL: X6S; Manuf_PN: GRM21BC81A226M; Manuf_name: MURATA ERIE N.A. INC TAIWAN BRANCH Okayama Murata Mfg.Co.,Ltd.Wakura Murata Mfg.; Manuftr: MUR; Part_Type: *LF_C0805; TOLERANCE: 20%; VOLTAGE: 10V
C1128 C1133 = CAP_NP: CAP CHIP 2.2UF 10V(+-10%.X7R.0603); CLASS: DISCRETE; MATERIAL: X7R; Manuf_PN: GRM188R71A225K; Manuf_name: MURATA ERIE N.A. INC TAIWAN BRANCH Okayama Murata Mfg.Co..Ltd.Wakura Murata Mfg.; Manuftr: MUR; Part_Type: *LF_C0603; TOLERANCE: 10%; VOLTAGE: 10V
J59 = DIP_2PIN: CONN DIP HEADER 2P 1R MS(P2.54,H8.6); CLASS: IO; DIP_SMD: DIP; ESD_CDM: NA; ESD_HBM: NA; ESD_MM: NA; MATERIAL: IO; MSD: NA; Manuf_PN: G2100HT0038-066-H; Manuf_name: WIESON ELECTRONIC CO.,LTD. (Wieson International; Manuftr: WSE; PIN_LENGTH_LONG_PIN: 119 MILS; PIN_LENGTH_SHORT_PIN: 119 MILS; Part_Type: *LF_Connector
L14 = L: EMI FILTER BLM15PX121SN1D(120,2A); CLASS: DISCRETE; Current_Amp: 2A; MATERIAL: IND; Manuf_name: MURATA ERIE N.A. INC TAIWAN BRANCH Okayama Murata Mfg.Co.,Ltd.Wakura Murata Mfg.; Manuftr: MUR; Part_Type: *LF_Inductor
OSC1 = OSC-4: OSC SMD 25MHZ(+-25PPM,3.3V)FJ2500009; CLASS: IO; MATERIAL: MISC; Manuf_PN: FJ2500009; Manuf_name: ECERA COMTEK CORPORATION (Pericom SaRonix Ecera Technology Corporation) P.S.E; Manuftr: ERC; Part_Type: *LF_Misc
R3766 = R: RES CHIP 0.51 1/16W +-1%(0402); CLASS: DISCRETE; MATERIAL: CHIP; Manuf_PN: RL0402FR-070R51L; Manuf_name: YAGEO CORPORATION; Manuftr: YGO; Part_Type: *LF_Resistor; TOLERANCE: 1%; WATTAGE: 1/16W
R4229 = R: RES CHIP 22 1/16W +-1%(0402); CLASS: DISCRETE; MATERIAL: CHIP; Manuf_PN: CR0222R0F002S; Manuf_name: RTECH TECHNOLOGY CO..LTD. (Compostar); Manuftr: RHT; Not_insert: NI; Part_Type: *LF_Resistor; TOLERANCE: 1%; WATTAGE: 1/16W
R4287 = R: RES CHIP 100K 1/16W +-1% (0402); CLASS: DISCRETE; MATERIAL: CHIP; Manuf_PN: RR0510S-104-FN; Manuf_name: CYNTEC CO.. LTD.; Manuftr: CYN; Part_Type: *LF_Resistor; TOLERANCE: 1%; WATTAGE: 1/16W
SW5 = SW3P_SC12PACQR: SWITCH DIP SLIDE(SC12P-ACWQR); CLASS: IO; DIP_SMD: DIP; ESD_CDM: N/A; ESD_HBM: N/A; ESD_MM: N/A; MATERIAL: MECH; MSD: NA; Manuf_PN: SC12P-ACWQR; Manuf_name: Diptronics Manufacturing Inc.; Manuftr: DIP; PIN_LENGTH_LONG_PIN: 99 MILS; PIN_LENGTH_SHORT_PIN: 40 MILS; Part_Type: *LF_Mech
C1158 C1159 = CAP_NP: CAP CHIP 47P 50V(+-5%.NPO.0402); CLASS: DISCRETE; MATERIAL: NPO; Manuf_PN: C1005NP0470JGT; Manuf_name: ACER PERIPHERALS INC.(Darfon Electronics Corp.); Manuftr: API; Part_Type: *LF_C0402; TOLERANCE: 5%; VOLTAGE: 50V
R3903 = R: RES CHIP 51K 1/16W +-1%(0402); CLASS: DISCRETE; MATERIAL: CHIP; Manuf_PN: RM04FTN5102; Manuf_name: TA-I TECHNOLOGY CO..LTD.; Manuftr: TAI; Part_Type: *LF_Resistor; TOLERANCE: 1%; WATTAGE: 1/16W
R3905 = R: RESISTOR CHIP 8.25K 1/16W+-1%(0402); CLASS: DISCRETE; MATERIAL: CHIP; Manuf_PN: CR028K25F002S; Manuf_name: YAGEO CORPORATION; Manuftr: YGO; Part_Type: *LF_Resistor; TOLERANCE: 1%; WATTAGE: 1/16W
R3906 = R: RES CHIP 0 1/16W +-5%(0402)EF; CLASS: DISCRETE; FPLIST: R0402,R0402-0201; MATERIAL: CHIP; Manuf_PN: WR04X000PTR; Manuf_name: WALSIN TECHNOLOGY CORPORATION; Manuftr: WTC; Part_Type: *LF_Resistor; TOLERANCE: 5%; WATTAGE: 1/16W
R3908 = R: RES CHIP 5.11K 1/16W +-1%(0402); CLASS: DISCRETE; MATERIAL: CHIP; Manuf_PN: RR0510S-5111-FN; Manuf_name: CYNTEC CO.. LTD.; Manuftr: CYN; Part_Type: *LF_Resistor; TOLERANCE: 1%; WATTAGE: 1/16W
R3910 = R: RES CHIP 34K 1/16W +-1%(0402)EF; CLASS: DISCRETE; MATERIAL: CHIP; Manuf_PN: WR04X3402FTR; Manuf_name: WALSIN TECHNOLOGY CORPORATION; Manuftr: WTC; Part_Type: *LF_Resistor; TOLERANCE: 1%; WATTAGE: 1/16W

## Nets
GND: C44.1 C45.2 C46.2 C1115.2 C1116.2 C1117.2 C1118.2 C1119.2 C1120.2 C1121.2 C1122.2 C1123.2 C1124.2 C1125.2 C1126.2 C1127.2 C1128.2 C1129.2 C1130.2 C1131.2 C1132.2 C1133.2 C1154.2 C1155.2 C1156.2 C1157.2 C1158.2 C1159.2 C1177.2 C1186.2 C1187.2 C1202.2 C1203.2 C1204.2 C1205.2 J56.G1 J56.G2 J59.1 OSC1.2(GND) Q52.S(SOURCE) Q53.S(SOURCE) R15.1 R17.2 R18.2 R20.1 R22.1 R2849.2 R2850.2 R2851.2 R2852.2 R2853.2 R2854.2 R2936.2 R2937.2 R2938.2 R2939.2 R2940.2 R2941.2 R3803.2 R3904.2 R3905.2 R3910.2 R4158.1 R4161.1 R4162.1 R4275.1 R4276.1 R4277.1 R4278.1 R4279.1 R4280.1 R4281.1 R4282.1 R4283.1 R4284.1 R4285.1 R4286.1 R4287.2 R4338.2 R4339.2 R4340.2 SW5.C(c) U6.4(VSS) U7.4(GND) U8.4(GND) U86.A1(GND21) U86.A2(GND24) U86.A18(GND22) U86.A19(GND23) U86.B1(GND25) U86.B19(GND26) U86.D18(GNDX2) U86.F10(GND15) U86.G4(GNDA) U86.G5(VREFA-) U86.H10(GND18) U86.H11(GND19) U86.H12(GND20) U86.J11(GND16) U86.J12(GND17) U86.K6(GND13) U86.K9(GND14) U86.K10(GND10) U86.K13(GND11) U86.K14(GND12) U86.L8(GND1) U86.L9(GND2) U86.M8(GND3) U86.M9(GND4) U86.M10(GND9) U86.N10(GND5) U86.P16(GND27) U86.R17(GND28) U86.R18(GNDX) U86.V1(GND6) U86.W1(GND7) U86.W2(GND8) U101.9(VSS) U101.TH U102.7(GND) U103.7(GND) U104.7(GND) U105.7(GND) ; also on sheet 12 13 17 18 19 20 21 22 23 24 25 26 27 28 29 30 31 32 33 34 35 36 37 38 39 40 41 42 52 53 54 55 56 57 58 61 62 63 64 65 66 67
P0V92: R3906.1 ; also on sheet 57 64 65
P0V92_BIC_SCALED: C1159.1 R3906.2 U86.H2(PE1|AIN2)
P1V8: C1202.1 C1203.1 C1204.1 C1205.1 R3909.1 R4312.1 R4313.1 R4314.1 R4315.1 R4316.1 R4317.1 R4318.1 R4319.1 R4320.1 R4321.1 R4322.1 R4323.1 R4386.1 U102.14(VCC) U103.14(VCC) U104.14(VCC) U105.14(VCC) ; also on sheet 17 18 19 22 23 24 25 26 27 28 29 30 31 32 33 34 35 36 37 53 58 62 65 67
P1V8_BIC_SCALED: C1158.1 R3909.2 R3910.1 U86.H3(PE0|AIN3)
P1V8_DISCHARGE_EN: Q52.G(GATE) Q53.D(DRAIN) R4385.2
P1V8_DISCHARGE_EN_D: Q52.D(DRAIN) R4386.2
P1V8_EN: Q53.G(GATE) ; also on sheet 12 58
P3V3: R4182.2 R4183.2 R4184.2 R4185.2 R4186.2 R4187.2 R4188.2 R4189.2 R4190.2 R4191.2 R4192.2 R4193.2 ; also on sheet 23
P3V3_M2A_EN: U86.M1(PC5|FAN0TACH0) ; also on sheet 38 54
P3V3_M2B_EN: U86.K3(PC7|FAN0TACH1) ; also on sheet 38 54
P3V3_M2C_EN: U86.V6(PF1|FAN0TACH2) ; also on sheet 38 54
P3V3_M2D_EN: U86.W7(PF5|FAN0TACH4) ; also on sheet 38 54
P3V3_M2E_EN: U86.U8(PF7|FAN0TACH5) ; also on sheet 38 54
P3V3_M2F_EN: U86.T14(PG1|FAN0TACH6) ; also on sheet 38 54
P3V3_M2G_EN: U86.A5(PE4|FAN0TACH7) ; also on sheet 38 55
P3V3_M2H_EN: U86.R2(PH1|LPC0COMXCTS) ; also on sheet 38 55
P3V3_M2I_EN: U86.R1(PH2|LPC0COMXDCD) ; also on sheet 38 55
P3V3_M2J_EN: U86.T1(PH3|LPC0COMXDSR) ; also on sheet 38 55
P3V3_M2K_EN: U86.R3(PH4|LPC0COMXDTR) ; also on sheet 38 55
P3V3_M2L_EN: U86.T2(PH5|LPC0COMXRI) ; also on sheet 38 55
P3V3_STBY: C44.2 C45.1 C46.1 C1115.1 C1116.1 C1117.1 C1118.1 C1119.1 C1120.1 C1121.1 C1122.1 C1123.1 C1124.1 C1129.1 C1130.1 C1133.1 C1154.1 C1155.1 C1177.1 C1186.1 C1187.1 D17.A L14.2 R16.1 R19.1 R21.1 R23.1 R24.1 R2791.1 R2792.1 R2793.1 R2794.1 R2795.1 R2796.1 R2930.1 R2931.1 R2932.1 R2933.1 R2934.1 R2935.1 R3765.1 R3786.1 R3787.1 R3788.1 R3789.1 R3790.1 R3791.1 R3792.1 R3793.1 R3794.1 R3795.1 R3796.1 R3797.1 R3798.1 R3799.1 R3800.1 R3801.1 R3882.1 R3883.1 R3884.1 R3908.1 R4048.1 R4051.1 R4052.1 R4055.1 R4056.1 R4097.1 R4163.2 R4206.2 R4207.2 R4208.2 R4209.2 R4210.2 R4211.2 R4212.2 R4213.2 R4214.2 R4215.2 R4216.2 R4217.2 R4341.1 R4342.1 R4343.1 R4385.1 U6.8(VCC) U7.8(V+) U8.8(V+) U86.F3(VDDA) U86.F4(VREFA+) U86.G10(VDD13) U86.H9(VDD14) U86.J8(VDD3) U86.J9(VDD4) U86.J10(VDD15) U86.K7(VDD11) U86.K8(VDD12) U86.K11(VDD9) U86.K12(VDD10) U86.L10(VDD1) U86.L11(VDD2) U86.L12(VDD5) U86.M11(VDD6) U86.M12(VDD7) U86.N16(VDD17) U86.P10(VDD8) U86.P17(VDD16) U86.P19(VBAT) U101.21(VDD) ; also on sheet 12 17 18 19 20 22 23 24 25 26 27 28 29 30 31 32 33 34 35 36 37 38 39 40 41 42 52 53 54 55 56 57 58 61 67
P3V3_STBY_BIC_SCALED: C1157.1 R3905.1 R3908.2 U86.G1(PE2|AIN1)
P12V_BIC_SCALED: C1156.1 R3903.2 R3904.1 U86.G2(PE3|AIN0)
P12V_STBY: R3903.1 ; also on sheet 42 56 61
VDDC_OUTPUT: C1125.1 C1126.1 C1127.1 C1128.1 U86.E10(VDDC2) U86.H16(VDDC1)
BIC_BOARD_ID_0: R4338.1 R4341.2 U86.B14(PS2|GPIOPS2)
BIC_BOARD_ID_1: R4339.1 R4342.2 U86.A14(PS3|GPIOPS3)
BIC_BOARD_ID_2: R4340.1 R4343.2 U86.V9(PS4|GPIOPS4)
BIC_REMOTE_DEBUG_SELECT_N: R4287.1 SW5.B(COM) U86.U2(PH6|GPIOPH6)
BMC_BYPASS_SELECT_N: J59.2 R4048.2 U86.P18(RESET_N)
BMC_HARTBEAT_LED_R_N: R3802.2 U86.T13(PS5|GPIOPS5)
BMC_HEARTBEAT_LED_N: D17.C R3802.1
CLK_25M_MINIBMC_CLKIN: OSC1.3(OUT) R3764.1
CLK_25M_MINIBMC_CLKIN_R: R3764.2 U86.E19(OSC0)
CLKBUF_M2A_OE_N: R2796.2 R2854.1 R4146.2 ; also on sheet 20
CLKBUF_M2A_OE_N_R: R4146.1 U101.1(P00)
CLKBUF_M2B_OE_N: R2795.2 R2853.1 R4147.2 ; also on sheet 20
CLKBUF_M2B_OE_N_R: R4147.1 U101.2(P01)
CLKBUF_M2C_OE_N: R2794.2 R2852.1 R4148.2 ; also on sheet 20
CLKBUF_M2C_OE_N_R: R4148.1 U101.3(P02)
CLKBUF_M2D_OE_N: R2793.2 R2851.1 R4149.2 ; also on sheet 20
CLKBUF_M2D_OE_N_R: R4149.1 U101.4(P03)
CLKBUF_M2E_OE_N: R2792.2 R2850.1 R4150.2 ; also on sheet 20
CLKBUF_M2E_OE_N_R: R4150.1 U101.5(P04)
CLKBUF_M2F_OE_N: R2791.2 R2849.1 R4151.2 ; also on sheet 20
CLKBUF_M2F_OE_N_R: R4151.1 U101.6(P05)
CLKBUF_M2G_OE_N: R2935.2 R2941.1 R4152.2 ; also on sheet 20
CLKBUF_M2G_OE_N_R: R4152.1 U101.7(P06)
CLKBUF_M2H_OE_N: R2934.2 R2940.1 R4153.2 ; also on sheet 20
CLKBUF_M2H_OE_N_R: R4153.1 U101.8(P07)
CLKBUF_M2I_OE_N: R2933.2 R2939.1 R4154.2 ; also on sheet 20
CLKBUF_M2I_OE_N_R: R4154.1 U101.10(P10)
CLKBUF_M2J_OE_N: R2932.2 R2938.1 R4155.2 ; also on sheet 20
CLKBUF_M2J_OE_N_R: R4155.1 U101.11(P11)
CLKBUF_M2K_OE_N: R2931.2 R2937.1 R4156.2 ; also on sheet 20
CLKBUF_M2K_OE_N_R: R4156.1 U101.12(P12)
CLKBUF_M2L_OE_N: R2930.2 R2936.1 R4157.2 ; also on sheet 20
CLKBUF_M2L_OE_N_R: R4157.1 U101.13(P13)
FM_BIC_DEBUG_EN: R4232.2 ; also on sheet 42
FM_BIC_DEBUG_EN_R: R4232.1 U86.B11(PN1|U1CTS)
FM_BIC_M2A_EN: R4057.2 R4275.2 ; also on sheet 54
FM_BIC_M2A_EN_R: R4057.1 U86.B13(PP2|USB0NXT)
FM_BIC_M2B_EN: R4058.2 R4276.2 ; also on sheet 54
FM_BIC_M2B_EN_R: R4058.1 U86.A16(PB0|USB0ID)
FM_BIC_M2C_EN: R4059.2 R4277.2 ; also on sheet 54
FM_BIC_M2C_EN_R: R4059.1 U86.R7(PA7|USB0EPEN)
FM_BIC_M2D_EN: R4060.2 R4278.2 ; also on sheet 54
FM_BIC_M2D_EN_R: R4060.1 U86.R13(PS7|GPIOPS7)
FM_BIC_M2E_EN: R4061.2 R4279.2 ; also on sheet 54
FM_BIC_M2E_EN_R: R4061.1 U86.U12(PN7|GPIOPN7)
FM_BIC_M2F_EN: R4062.2 R4280.2 ; also on sheet 54
FM_BIC_M2F_EN_R: R4062.1 U86.B16(PB1|USB0VBUS)
FM_BIC_M2G_EN: R4089.2 R4281.2 ; also on sheet 55
FM_BIC_M2G_EN_R: R4089.1 U86.D8(PP4|GPIOPP4)
FM_BIC_M2H_EN: R4090.2 R4282.2 ; also on sheet 55
FM_BIC_M2H_EN_R: R4090.1 U86.A8(PP7|GPIOPP7)
FM_BIC_M2I_EN: R4091.2 R4283.2 ; also on sheet 55
FM_BIC_M2I_EN_R: R4091.1 U86.M3(PQ7|GPIOPQ7)
FM_BIC_M2J_EN: R4092.2 R4284.2 ; also on sheet 55
FM_BIC_M2J_EN_R: R4092.1 U86.P3(PR4|GPIOPR4)
FM_BIC_M2K_EN: R4093.2 R4285.2 ; also on sheet 55
FM_BIC_M2K_EN_R: R4093.1 U86.R10(PR7|GPIOPR7)
FM_BIC_M2L_EN: R4094.2 R4286.2 ; also on sheet 55
FM_BIC_M2L_EN_R: R4094.1 U86.D12(PS0|GPIOPS0)
FM_COM_EN_N: R4006.1 ; also on sheet 52
FM_COM_EN_N_R: R4006.2 U86.D13(PS1|LPC0RESET_N)
FM_COM_SEL_0: R4007.1 ; also on sheet 52
FM_COM_SEL_0_R: R4007.2 U86.H19(PL1|LPC0CLK)
FM_COM_SEL_1: R4008.1 ; also on sheet 52
FM_COM_SEL_1_R: R4008.2 U86.G16(PL0|LPC0FRAME_N)
FM_COM_SEL_2: R4009.1 ; also on sheet 52
FM_COM_SEL_2_R: R4009.2 U86.J18(PL3|LPC0SERIRQ)
FM_COM_SEL_3: R4010.1 ; also on sheet 52
FM_COM_SEL_3_R: R4010.2 U86.L19(PM3|LPC0AD0)
FM_JTAG_EN_N: R4011.1 ; also on sheet 52
FM_JTAG_EN_N_R: R4011.2 U86.K19(PM1|LPC0AD2)
FM_JTAG_SEL_0: R4012.1 ; also on sheet 52
FM_JTAG_SEL_0_R: R4012.2 U86.K18(PM0|LPC0AD3)
FM_JTAG_SEL_1: R4013.1 ; also on sheet 52
FM_JTAG_SEL_1_R: R4013.2 U86.G19(PL5|LPC0PD_N)
FM_JTAG_SEL_2: R4014.1 ; also on sheet 52
FM_JTAG_SEL_2_R: R4014.2 U86.H18(PL4|LPC0SCI_N)
FM_JTAG_SEL_3: R4015.1 ; also on sheet 52
FM_JTAG_SEL_3_R: R4015.2 U86.G18(PL2|LPC0CLKRUN_N)
FM_PLD_VCCIO_1_5_P1V8: R4228.1 ; also on sheet 53
FM_PLD_VCCIO_1_5_P1V8_R: R4228.2 U86.K1(PK2|GPIOPK2)
FM_PLD_VCCIO_1_5_P3V3SB: R4229.1 ; also on sheet 53
FM_PLD_VCCIO_1_5_P3V3SB_R: R4229.2 U86.K2(PK3|GPIOPK3)
FM_POWER_EN: U86.W10(PT0|GPIOPT0) ; also on sheet 12 38
FRU_ADDR0: R16.2 U6.1(E0)
FRU_ADDR1: R17.1 U6.2(E1)
FRU_ADDR2: R18.1 U6.3(E2)
I2C_GPIO_INT_N: R4163.1 U101.22(INT#)
I2C_PESW_MULTI_CONFIG_ADD0: R3748.2 ; also on sheet 22
I2C_PESW_MULTI_CONFIG_ADD0_R: R3748.1 U86.M2(PC4|FAN0PWM0)
I2C_PESW_MULTI_CONFIG_ADD1: R3752.2 ; also on sheet 22
I2C_PESW_MULTI_CONFIG_ADD1_R: R3752.1 U86.L2(PC6|FAN0PWM1)
I2C_PESW_MULTI_CONFIG_ADD2: R3756.2 ; also on sheet 22
I2C_PESW_MULTI_CONFIG_ADD2_R: R3756.1 U86.U6(PF0|FAN0PWM2)
I2C_PESW_MULTI_CONFIG_ADD3: R4063.2 ; also on sheet 22
I2C_PESW_MULTI_CONFIG_ADD3_R: R4063.1 U86.V7(PF4|FAN0PWM4)
I2C_PESW_MULTI_CONFIG_ADD4: R4064.2 ; also on sheet 22
I2C_PESW_MULTI_CONFIG_ADD4_R: R4064.1 U86.N15(PG0|FAN0PWM6)
JTAG_BIC_M2_TCK: R3990.1 ; also on sheet 52
JTAG_BIC_M2_TCK_R: R3990.2 U86.V12(PG6|RMII0-EN0RXER)
JTAG_BIC_M2_TDI: R3991.1 ; also on sheet 52
JTAG_BIC_M2_TDI_R: R3991.2 U86.M16(PG3|RMII0-EN0TXEN)
JTAG_BIC_M2_TDO: U86.K15(PG5|RMII0-EN0TXD1) ; also on sheet 52
JTAG_BIC_M2_TMS: R3992.1 ; also on sheet 52
JTAG_BIC_M2_TMS_R: R3992.2 U86.K17(PG4|RMII0-EN0TXD0)
JTAG_BIC_M2_TRST: R3803.1 R3993.1 ; also on sheet 52
JTAG_BIC_M2_TRST_R: R3993.2 U86.U14(PG7|RMII0-EN0RXDV)
JTAG_TI_TCK: J56.4 R3878.2 R3882.2
JTAG_TI_TCK_R: R3878.1 U86.B15(PC0|TCK|SWDCLK)
JTAG_TI_TDI: J56.3 R3879.2 R3883.2
JTAG_TI_TDI_R: R3879.1 U86.D14(PC2|TDI)
JTAG_TI_TDO: J56.2 R3880.2
JTAG_TI_TDO_R: R3880.1 U86.C14(PC3|TDO|SWO)
JTAG_TI_TMS: J56.1 R3881.2 R3884.2
JTAG_TI_TMS_R: R3881.1 U86.C15(PC1|TMS|SWDIO)
OSC1_VDD: C1131.1 L14.1 OSC1.4(VDD) R3766.1
OSC1_VDD_R: C1132.1 R3766.2
PD_FRU_WC_N: R15.2 U6.7(~{WC})
PD_I2C_GPIO_A0: R4158.2 U101.18(A0)
PD_I2C_GPIO_A1: R4161.2 U101.23(A1)
PD_I2C_GPIO_A2: R4162.2 U101.24(A2)
PU_25M_BMC_CLK_EN_R: OSC1.1(OE) R3765.2
PU_REMOTE_DEBUG_SELECT: R4097.2 SW5.A(a)
PWRGD_GPV2_SYS: U86.A13(PQ4|DIVSCLK) ; also on sheet 67
PWRGD_P3V3_M2A: U86.A11(PN2|U1DCD) ; also on sheet 39
PWRGD_P3V3_M2B: U86.B10(PN3|U1DSR) ; also on sheet 39
PWRGD_P3V3_M2C: U86.A10(PN4|U1DTR) ; also on sheet 39
PWRGD_P3V3_M2D: U86.B9(PN5|U1RI) ; also on sheet 39
PWRGD_P3V3_M2E: U86.C10(PN0|U1RTS) ; also on sheet 40
PWRGD_P3V3_M2F: U86.C8(PJ0|PECIVTT) ; also on sheet 40
PWRGD_P3V3_M2G: U86.E7(PJ1|PECI0SD) ; also on sheet 40
PWRGD_P3V3_M2H: U86.D6(PP0|SGPMCLK) ; also on sheet 40
PWRGD_P3V3_M2I: U86.D7(PP1|SGPMLD) ; also on sheet 41
PWRGD_P3V3_M2J: U86.A7(PE6|SGPMO) ; also on sheet 41
PWRGD_P3V3_M2K: U86.G15(PM5|SGPMI) ; also on sheet 41
PWRGD_P3V3_M2L: U86.V10(PT1|GPIOPT1) ; also on sheet 41
RST_I2C_MUX1_N: R4028.1 ; also on sheet 36
RST_I2C_MUX1_N_R: R4028.2 U86.H17(PJ2|GPIOPJ2)
RST_I2C_MUX2_N: R4029.1 ; also on sheet 36
RST_I2C_MUX2_N_R: R4029.2 U86.F16(PJ3|GPIOPJ3)
RST_I2C_MUX3_N: R4030.1 ; also on sheet 36
RST_I2C_MUX3_N_R: R4030.2 U86.F18(PJ4|GPIOPJ4)
RST_I2C_MUX4_N: R4031.1 ; also on sheet 37
RST_I2C_MUX4_N_R: R4031.2 U86.E17(PJ5|GPIOPJ5)
RST_I2C_MUX5_N: R4032.1 ; also on sheet 37
RST_I2C_MUX5_N_R: R4032.2 U86.N1(PJ6|GPIOPJ6)
RST_I2C_MUX6_N: R4033.1 ; also on sheet 37
RST_I2C_MUX6_N_R: R4033.2 U86.K5(PJ7|GPIOPJ7)
RST_I2C_MUX7_N: R4382.1 ; also on sheet 61
RST_I2C_MUX7_N_R: R4382.2 U86.V2(PH7|GPIOPH7)
RST_PE_N: U86.E18(PT2|GPIOPT2) ; also on sheet 12 67
RST_PE_SLOT1_1_RESET_N: R4337.1 ; also on sheet 12
RST_PE_SLOT1_1_RESET_N_R: R4337.2 U86.F17(PT3|GPIOPT3)
RST_PESW_M2A_LVC_N: R4164.2 ; also on sheet 24
RST_PESW_M2A_LVC_N_R: R4164.1 R4186.1 U103.2(OUT)
RST_PESW_M2A_N: U103.1(IN) ; also on sheet 17
RST_PESW_M2B_LVC_N: R4165.2 ; also on sheet 25
RST_PESW_M2B_LVC_N_R: R4165.1 R4187.1 U103.4(OUT)
RST_PESW_M2B_N: U103.3(IN) ; also on sheet 17
RST_PESW_M2C_LVC_N: R4166.2 ; also on sheet 26
RST_PESW_M2C_LVC_N_R: R4166.1 R4182.1 U103.6(OUT)
RST_PESW_M2C_N: U103.5(IN) ; also on sheet 17
RST_PESW_M2D_LVC_N: R4167.2 ; also on sheet 27
RST_PESW_M2D_LVC_N_R: R4167.1 R4183.1 U103.8(OUT)
RST_PESW_M2D_N: U103.9(IN) ; also on sheet 17
RST_PESW_M2E_LVC_N: R4169.2 ; also on sheet 28
RST_PESW_M2E_LVC_N_R: R4169.1 R4184.1 U103.10(OUT)
RST_PESW_M2E_N: U103.11(IN) ; also on sheet 17
RST_PESW_M2F_LVC_N: R4173.2 ; also on sheet 29
RST_PESW_M2F_LVC_N_R: R4173.1 R4185.1 U103.12(OUT)
RST_PESW_M2F_N: U103.13(IN) ; also on sheet 17
RST_PESW_M2G_LVC_N: R4168.2 ; also on sheet 30
RST_PESW_M2G_LVC_N_R: R4168.1 R4192.1 U102.2(OUT)
RST_PESW_M2G_N: U102.1(IN) ; also on sheet 17
RST_PESW_M2H_LVC_N: R4170.2 ; also on sheet 31
RST_PESW_M2H_LVC_N_R: R4170.1 R4193.1 U102.4(OUT)
RST_PESW_M2H_N: U102.3(IN) ; also on sheet 17
RST_PESW_M2I_LVC_N: R4171.2 ; also on sheet 32
RST_PESW_M2I_LVC_N_R: R4171.1 R4188.1 U102.6(OUT)
RST_PESW_M2I_N: U102.5(IN) ; also on sheet 17
RST_PESW_M2J_LVC_N: R4172.2 ; also on sheet 33
RST_PESW_M2J_LVC_N_R: R4172.1 R4189.1 U102.8(OUT)
RST_PESW_M2J_N: U102.9(IN) ; also on sheet 17
RST_PESW_M2K_LVC_N: R4174.2 ; also on sheet 34
RST_PESW_M2K_LVC_N_R: R4174.1 R4190.1 U102.10(OUT)
RST_PESW_M2K_N: U102.11(IN) ; also on sheet 17
RST_PESW_M2L_LVC_N: R4175.2 ; also on sheet 35
RST_PESW_M2L_LVC_N_R: R4175.1 R4191.1 U102.12(OUT)
RST_PESW_M2L_N: U102.13(IN) ; also on sheet 17
SMB_BIC_3V3SB_READY_N: R4035.2 ; also on sheet 12
SMB_BIC_3V3SB_READY_N_R: R4035.1 U86.T8(PF6|FAN0PWM5)
SMB_BIC_VR_CLK: R3911.2 ; also on sheet 61
SMB_BIC_VR_CLK_R2: R3911.1 R4051.2 U86.V3(PA0|U0Rx)
SMB_BIC_VR_DAT: R3912.2 ; also on sheet 61
SMB_BIC_VR_DAT_R2: R3912.1 R4052.2 U86.W3(PA1|U0Tx)
SMB_BMC_3V3SB_CLK: R3783.1 ; also on sheet 12
SMB_BMC_3V3SB_CLK_R2: R3783.2 U86.D2(PD2|I2C8SCL)
SMB_BMC_3V3SB_DAT: R3784.1 ; also on sheet 12
SMB_BMC_3V3SB_DAT_R2: R3784.2 U86.D1(PD3|I2C8SDA)
SMB_INA230_ALERT_N: U86.B5(PE5|FAN0PWM7|GPIO) ; also on sheet 61
SMB_M2A_ALERT_LVC_N: R4194.2 U86.M18(PM4|RMII0-EN0RREF_CLK)
SMB_M2A_ALERT_LVC_N_R: R4194.1 R4210.1 U105.2(OUT)
SMB_M2A_ALERT_N: R4312.2 U105.1(IN) ; also on sheet 24
SMB_M2A_INA231_ALRT_N: U86.U10(PS6|GPIOPS6) ; also on sheet 24
SMB_M2AB_3V3SB_CLK: R3771.1 ; also on sheet 36
SMB_M2AB_3V3SB_CLK_R2: R3771.2 R3790.2 U86.B12(PP5|I2C2SCL)
SMB_M2AB_3V3SB_DAT: R3772.1 ; also on sheet 36
SMB_M2AB_3V3SB_DAT_R2: R3772.2 R3791.2 U86.B8(PP6|I2C2SDA)
SMB_M2B_ALERT_LVC_N: R4195.2 U86.W6(PF2|RMII0-EN0MDC)
SMB_M2B_ALERT_LVC_N_R: R4195.1 R4211.1 U105.4(OUT)
SMB_M2B_ALERT_N: R4313.2 U105.3(IN) ; also on sheet 25
SMB_M2B_INA231_ALRT_N: U86.B2(PD7|AIN4) ; also on sheet 25
SMB_M2C_ALERT_LVC_N: R4196.2 U86.T7(PF3|RMII0-EN0MDIO)
SMB_M2C_ALERT_LVC_N_R: R4196.1 R4206.1 U105.6(OUT)
SMB_M2C_ALERT_N: R4314.2 U105.5(IN) ; also on sheet 26
SMB_M2C_INA231_ALRT_N: U86.B3(PD6|AIN5) ; also on sheet 26
SMB_M2CD_3V3SB_CLK: R3773.1 ; also on sheet 36
SMB_M2CD_3V3SB_CLK_R2: R3773.2 R3792.2 U86.U19(PK4|I2C3SCL)
SMB_M2CD_3V3SB_DAT: R3774.1 ; also on sheet 36
SMB_M2CD_3V3SB_DAT_R2: R3774.2 R3793.2 U86.V17(PK5|I2C3SDA)
SMB_M2D_ALERT_LVC_N: R4197.2 U86.V5(PA6|EN0RXCK)
SMB_M2D_ALERT_LVC_N_R: R4197.1 R4207.1 U104.2(OUT)
SMB_M2D_ALERT_N: R4318.2 U104.1(IN) ; also on sheet 27
SMB_M2D_INA231_ALRT_N: U86.B4(PD5|AIN6) ; also on sheet 27
SMB_M2E_ALERT_LVC_N: R4199.2 U86.V11(PG2|EN0TXCK)
SMB_M2E_ALERT_LVC_N_R: R4199.1 R4208.1 U104.4(OUT)
SMB_M2E_ALERT_N: R4319.2 U104.3(IN) ; also on sheet 28
SMB_M2E_INA231_ALRT_N: U86.A4(PD4|AIN7) ; also on sheet 28
SMB_M2EF_3V3SB_CLK: R3775.1 ; also on sheet 36
SMB_M2EF_3V3SB_CLK_R2: R3775.2 R3794.2 U86.V16(PK6|I2C4SCL)
SMB_M2EF_3V3SB_DAT: R3776.1 ; also on sheet 36
SMB_M2EF_3V3SB_DAT_R2: R3776.2 R3795.2 U86.W16(PK7|I2C4SDA)
SMB_M2F_ALERT_LVC_N: R4203.2 U86.T12(PN6|EN0TXER)
SMB_M2F_ALERT_LVC_N_R: R4203.1 R4209.1 U104.6(OUT)
SMB_M2F_ALERT_N: R4320.2 U104.5(IN) ; also on sheet 29
SMB_M2F_INA231_ALRT_N: U86.W12(PQ5|RMII0-EN0RXD0) ; also on sheet 29
SMB_M2G_ALERT_LVC_N: R4198.2 U86.N18(PM7|EN0COL)
SMB_M2G_ALERT_LVC_N_R: R4198.1 R4216.1 U104.8(OUT)
SMB_M2G_ALERT_N: R4321.2 U104.9(IN) ; also on sheet 30
SMB_M2G_INA231_ALRT_N: U86.U15(PQ6|RMII0-EN0RXD1) ; also on sheet 30
SMB_M2GH_3V3SB_CLK: R3777.1 ; also on sheet 37
SMB_M2GH_3V3SB_CLK_R2: R3777.2 R3796.2 U86.C6(PB4|I2C5SCL)
SMB_M2GH_3V3SB_DAT: R3778.1 ; also on sheet 37
SMB_M2GH_3V3SB_DAT_R2: R3778.2 R3797.2 U86.B6(PB5|I2C5SDA)
SMB_M2H_ALERT_LVC_N: R4200.2 U86.N19(PM6|EN0CRS)
SMB_M2H_ALERT_LVC_N_R: R4200.1 R4217.1 U104.10(OUT)
SMB_M2H_ALERT_N: R4322.2 U104.11(IN) ; also on sheet 31
SMB_M2H_INA231_ALRT_N: U86.P4(PH0|LPC0COMXRTS) ; also on sheet 31
SMB_M2I_ALERT_LVC_N: R4201.2 U86.T6(PA2|SSI0CLK)
SMB_M2I_ALERT_LVC_N_R: R4201.1 R4212.1 U104.12(OUT)
SMB_M2I_ALERT_N: R4323.2 U104.13(IN) ; also on sheet 32
SMB_M2I_INA231_ALRT_N: U86.E3(PQ0|SSI3CLK) ; also on sheet 32
SMB_M2IJ_3V3SB_CLK: R3779.1 ; also on sheet 37
SMB_M2IJ_3V3SB_CLK_R2: R3779.2 R3798.2 U86.F2(PB6|I2C6SCL)
SMB_M2IJ_3V3SB_DAT: R3780.1 ; also on sheet 37
SMB_M2IJ_3V3SB_DAT_R2: R3780.2 R3799.2 U86.F1(PB7|I2C6SDA)
SMB_M2J_ALERT_LVC_N: R4202.2 U86.U5(PA3|SSI0FSS)
SMB_M2J_ALERT_LVC_N_R: R4202.1 R4213.1 U105.8(OUT)
SMB_M2J_ALERT_N: R4315.2 U105.9(IN) ; also on sheet 33
SMB_M2J_INA231_ALRT_N: U86.E2(PQ1|SSI3FSS) ; also on sheet 33
SMB_M2K_ALERT_LVC_N: R4204.2 U86.V4(PA4|SSI0XDAT0)
SMB_M2K_ALERT_LVC_N_R: R4204.1 R4214.1 U105.10(OUT)
SMB_M2K_ALERT_N: R4316.2 U105.11(IN) ; also on sheet 34
SMB_M2K_INA231_ALRT_N: U86.H4(PQ2|SSI3XDAT0) ; also on sheet 34
SMB_M2KL_3V3SB_CLK: R3781.1 ; also on sheet 37
SMB_M2KL_3V3SB_CLK_R2: R3781.2 R3800.2 U86.C2(PD0|I2C7SCL)
SMB_M2KL_3V3SB_DAT: R3782.1 ; also on sheet 37
SMB_M2KL_3V3SB_DAT_R2: R3782.2 R3801.2 U86.C1(PD1|I2C7SDA)
SMB_M2L_ALERT_LVC_N: R4205.2 U86.W4(PA5|SSI0XDAT1)
SMB_M2L_ALERT_LVC_N_R: R4205.1 R4215.1 U105.12(OUT)
SMB_M2L_ALERT_N: R4317.2 U105.13(IN) ; also on sheet 35
SMB_M2L_INA231_ALRT_N: U86.M4(PQ3|SSI3XDAT1) ; also on sheet 35
SMB_PESW_3V3SB_CLK: R3767.1 ; also on sheet 23
SMB_PESW_3V3SB_CLK_R2: R3767.2 R3786.2 U86.A17(PB2|I2C0SCL)
SMB_PESW_3V3SB_DAT: R3768.1 ; also on sheet 23
SMB_PESW_3V3SB_DAT_R2: R3768.2 R3787.2 U86.B17(PB3|I2C0SDA)
SMB_SENSOR_3V3SB_CLK: R42.2 R47.1 R3769.1 R4331.1 ; also on sheet 20
SMB_SENSOR_3V3SB_CLK_R1: R44.2 R4160.1 R4331.2 ; also on sheet 19 61
SMB_SENSOR_3V3SB_CLK_R2: R3769.2 R3788.2 U86.N5(PR0|I2C1SCL)
SMB_SENSOR_3V3SB_DAT: R41.2 R48.1 R3770.1 R4330.1 ; also on sheet 20
SMB_SENSOR_3V3SB_DAT_R1: R43.2 R4159.1 R4330.2 ; also on sheet 19 61
SMB_SENSOR_3V3SB_DAT_R2: R3770.2 R3789.2 U86.N4(PR1|I2C1SDA)
SMB_SENSOR_FRU_CLK_R1: R47.2 U6.6(SCL)
SMB_SENSOR_FRU_DAT_R1: R48.2 U6.5(SDA)
SMB_SENSOR_I2C_GPIO_CLK_R1: R4160.2 U101.19(SCL)
SMB_SENSOR_I2C_GPIO_DAT_R1: R4159.2 U101.20(SDA)
SMB_SENSOR_TMP75_CLK_0_R1: R42.1 U7.2(SCL)
SMB_SENSOR_TMP75_CLK_1_R1: R44.1 U8.2(SCL)
SMB_SENSOR_TMP75_DAT_0_R1: R41.1 U7.1(SDA)
SMB_SENSOR_TMP75_DAT_1_R1: R43.1 U8.1(SDA)
TMP_A0_0: R19.2 U7.7(A0)
TMP_A0_1: R22.2 U8.7(A0)
TMP_A1_0: R20.2 U7.6(A1)
TMP_A1_1: R23.2 U8.6(A1)
TMP_A2_0: R21.2 U7.5(A2)
TMP_A2_1: R24.2 U8.5(A2)
TMP_ALERT_U7_N: R4053.2 U86.N2(PR2|GPIOPR2)
TMP_ALERT_U7_N_R: R4053.1 R4055.2 U7.3(ALERT)
TMP_ALERT_U8_N: R4054.2 U86.V8(PR3|GPIOPR3)
TMP_ALERT_U8_N_R: R4054.1 R4056.2 U8.3(ALERT)
UART_BIC_RXD: U86.J1(PK0|U4RX) ; also on sheet 52
UART_BIC_RXD_REMOTE: U86.P2(PR5|U1RX) ; also on sheet 52
UART_BIC_TXD: R3885.2 ; also on sheet 52
UART_BIC_TXD_R: R3885.1 U86.J2(PK1|U4TX)
UART_BIC_TXD_REMOTE: R4095.2 ; also on sheet 52
UART_BIC_TXD_REMOTE_R: R4095.1 U86.W9(PR6|U1TX)

Not connected (* = marked no-connect by the designer): U86 B7(PE7|NMI) B18(PL7|USB0DM) C5(NC6)* C12(PP3|RTCCLK) C18(PL6|USB0DP) D19(OSC1)* E13(NC5)* L18(PM2|LPC0AD1) M17(HIB_N)* T18(XOSC0)* T19(XOSC1)* U18(WAKE_N)* V13(NC8)* V14(NC10)* V15(NC11)* V18(NC1)* V19(NC2)* W13(NC9)* W15(NC7)* W18(NC3)* W19(NC4)*; U101 14(P14)* 15(P15)* 16(P16)* 17(P17)*

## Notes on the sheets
sheet 43
- SMBus (8-bit) Address:0x40
- I2C GPIO
sheet 44
- Level Shifter (PM8545 to M.2, 1.8V to 3.3V)
- BOM Nore:
  R4386 change to FTT0349R9FTP
  (RES CHIP 49.9 1/10W +-1%(0603)EF)
- Discharge Circuit
- Level Shifter 3
sheet 45
- SMBus (8-bit) Address:0xA2
- FRU
- Write operations are
  enabled when WC is low
- SMBus (8-bit) Address:0x9A
- TEMP SENSOR
- SMBus (8-bit) Address:0x9C
- TEMP SENSOR
- TEMP SENSOR & FRU
sheet 46
- Heartbeat LED
- BIC Board ID
- PVT version
- BIC_SNOWFLAKE 1
sheet 47
- Note:
  R3764 place near OSC1
- STRAP HEADER
- Disable BIC
- Enable Remote Debug
- BIC_SNOWFLAKE 2
sheet 48
- BIC_SNOWFLAKE 3
sheet 49
- Level Shifter (M.2 to BIC, 1.8V to 3.3V)
- Level Shifter 4
sheet 50
- AVIN 0
- AVIN 1
- AVIN 2
- AVIN 3
- BIC-VOLTAGE MONITOR
